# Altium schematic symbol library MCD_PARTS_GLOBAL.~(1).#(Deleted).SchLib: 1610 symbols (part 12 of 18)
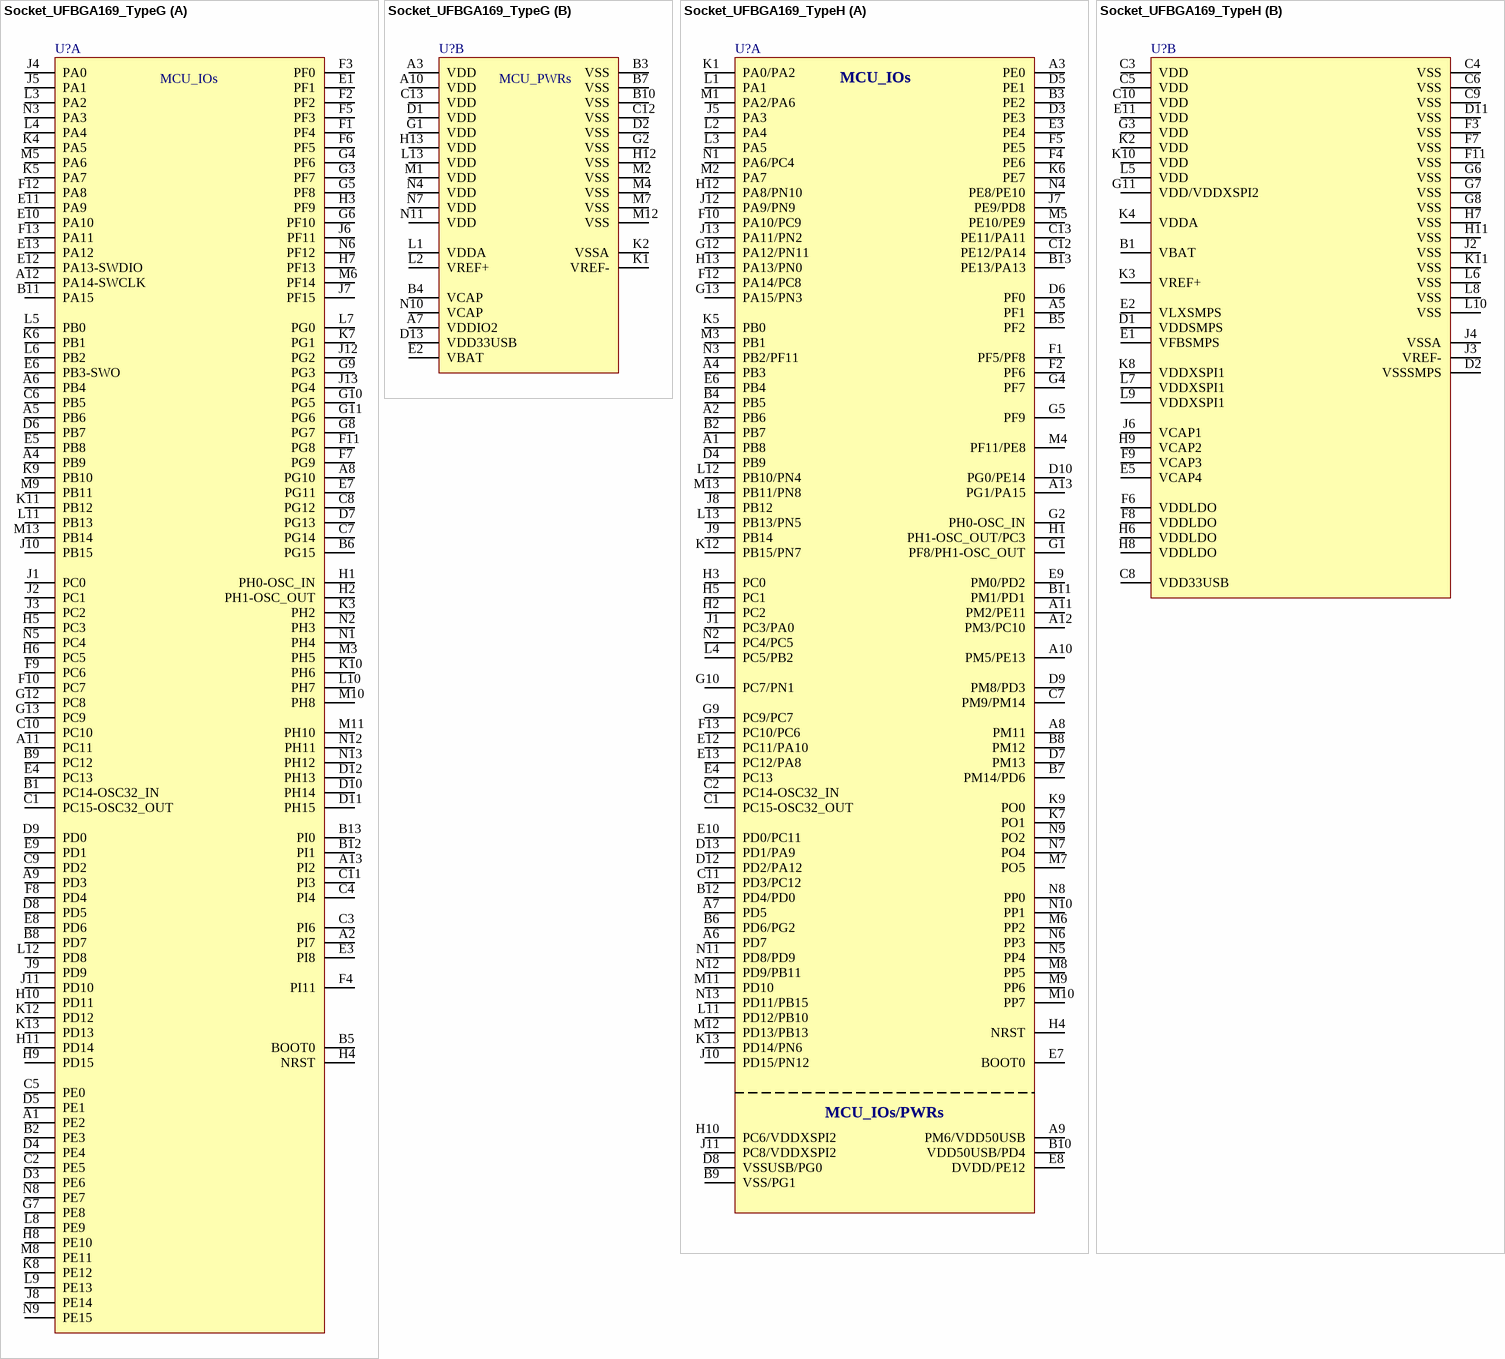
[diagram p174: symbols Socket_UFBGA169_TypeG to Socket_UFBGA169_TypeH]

## Socket_UFBGA169_TypeG
designator U?
part A pins: A1 PE2, A2 PI7, A4 PB9, A5 PB6, A6 PB4, A8 PG10, A9 PD3, A11 PC11, A12 PA14-SWCLK, A13 PI2, B1 PC14-OSC32_IN, B2 PE3, B5 BOOT0, B6 PG15, B8 PD7, B9 PC12, B11 PA15, B12 PI1, B13 PI0, C1 PC15-OSC32_OUT, C2 PE5, C3 PI6, C4 PI4, C5 PE0, C6 PB5, C7 PG14, C8 PG12, C9 PD2, C10 PC10, C11 PI3, D3 PE6, D4 PE4, D5 PE1, D6 PB7, D7 PG13, D8 PD5, D9 PD0, D10 PH14, D11 PH15, D12 PH13, E1 PF1, E3 PI8, E4 PC13, E5 PB8, E6 PB3-SWO, E7 PG11, E8 PD6, E9 PD1, E10 PA10, E11 PA9, E12 PA13-SWDIO, E13 PA12, F1 PF4, F2 PF2, F3 PF0, F4 PI11, F5 PF3, F6 PF5, F7 PG9, F8 PD4, F9 PC6, F10 PC7, F11 PG8, F12 PA8, F13 PA11, G3 PF7, G4 PF6, G5 PF8, G6 PF10, G7 PE8, G8 PG7, G9 PG3, G10 PG5, G11 PG6, G12 PC8, G13 PC9, H1 PH0-OSC_IN, H2 PH1-OSC_OUT, H3 PF9, H4 NRST, H5 PC3, H6 PC5, H7 PF13, H8 PE10, H9 PD15, H10 PD11, H11 PD14, J1 PC0, J2 PC1, J3 PC2, J4 PA0, J5 PA1, J6 PF11, J7 PF15, J8 PE14, J9 PD9, J10 PB15, J11 PD10, J12 PG2, J13 PG4, K3 PH2, K4 PA5, K5 PA7, K6 PB1, K7 PG1, K8 PE12, K9 PB10, K10 PH6, K11 PB12, K12 PD12, K13 PD13, L3 PA2, L4 PA4, L5 PB0, L6 PB2, L7 PG0, L8 PE9, L9 PE13, L10 PH7, L11 PB13, L12 PD8, M3 PH5, M5 PA6, M6 PF14, M8 PE11, M9 PB11, M10 PH8, M11 PH10, M13 PB14, N1 PH4, N2 PH3, N3 PA3, N5 PC4, N6 PF12, N8 PE7, N9 PE15, N12 PH11, N13 PH12
part B pins: A3 VDD, A7 VDDIO2, A10 VDD, B3 VSS, B4 VCAP, B7 VSS, B10 VSS, C12 VSS, C13 VDD, D1 VDD, D2 VSS, D13 VDD33USB, E2 VBAT, G1 VDD, G2 VSS, H12 VSS, H13 VDD, K1 VREF-, K2 VSSA, L1 VDDA, L2 VREF+, L13 VDD, M1 VDD, M2 VSS, M4 VSS, M7 VSS, M12 VSS, N4 VDD, N7 VDD, N10 VCAP, N11 VDD

## Socket_UFBGA169_TypeH
designator U?
part A pins: A1 PB8, A2 PB6, A3 PE0, A4 PB3, A5 PF1, A6 PD7, A7 PD5, A8 PM11, A9 PM6/VDD50USB, A10 PM5/PE13, A11 PM2/PE11, A12 PM3/PC10, A13 PG1/PA15, B2 PB7, B3 PE2, B4 PB5, B5 PF2, B6 PD6/PG2, B7 PM14/PD6, B8 PM12, B9 VSS/PG1, B10 VDD50USB/PD4, B11 PM1/PD1, B12 PD4/PD0, B13 PE13/PA13, C1 PC15-OSC32_OUT, C2 PC14-OSC32_IN, C7 PM9/PM14, C11 PD3/PC12, C12 PE12/PA14, C13 PE11/PA11, D3 PE3, D4 PB9, D5 PE1, D6 PF0, D7 PM13, D8 VSSUSB/PG0, D9 PM8/PD3, D10 PG0/PE14, D12 PD2/PA12, D13 PD1/PA9, E3 PE4, E4 PC13, E6 PB4, E7 BOOT0, E8 DVDD/PE12, E9 PM0/PD2, E10 PD0/PC11, E12 PC11/PA10, E13 PC12/PA8, F1 PF5/PF8, F2 PF6, F4 PE6, F5 PE5, F10 PA10/PC9, F12 PA14/PC8, F13 PC10/PC6, G1 PF8/PH1-OSC_OUT, G2 PH0-OSC_IN, G4 PF7, G5 PF9, G9 PC9/PC7, G10 PC7/PN1, G12 PA12/PN11, G13 PA15/PN3, H1 PH1-OSC_OUT/PC3, H2 PC2, H3 PC0, H4 NRST, H5 PC1, H10 PC6/VDDXSPI2, H12 PA8/PN10, H13 PA13/PN0, J1 PC3/PA0, J5 PA3, J7 PE9/PD8, J8 PB12, J9 PB14, J10 PD15/PN12, J11 PC8/VDDXSPI2, J12 PA9/PN9, J13 PA11/PN2, K1 PA0/PA2, K5 PB0, K6 PE7, K7 PO1, K9 PO0, K12 PB15/PN7, K13 PD14/PN6, L1 PA1, L2 PA4, L3 PA5, L4 PC5/PB2, L11 PD12/PB10, L12 PB10/PN4, L13 PB13/PN5, M1 PA2/PA6, M2 PA7, M3 PB1, M4 PF11/PE8, M5 PE10/PE9, M6 PP2, M7 PO5, M8 PP5, M9 PP6, M10 PP7, M11 PD10, M12 PD13/PB13, M13 PB11/PN8, N1 PA6/PC4, N2 PC4/PC5, N3 PB2/PF11, N4 PE8/PE10, N5 PP4, N6 PP3, N7 PO4, N8 PP0, N9 PO2, N10 PP1, N11 PD8/PD9, N12 PD9/PB11, N13 PD11/PB15
part B pins: B1 VBAT, C3 VDD, C4 VSS, C5 VDD, C6 VSS, C8 VDD33USB, C9 VSS, C10 VDD, D1 VDDSMPS, D2 VSSSMPS, D11 VSS, E1 VFBSMPS, E2 VLXSMPS, E5 VCAP4, E11 VDD, F3 VSS, F6 VDDLDO, F7 VSS, F8 VDDLDO, F9 VCAP3, F11 VSS, G3 VDD, G6 VSS, G7 VSS, G8 VSS, G11 VDD/VDDXSPI2, H6 VDDLDO, H7 VSS, H8 VDDLDO, H9 VCAP2, H11 VSS, J2 VSS, J3 VREF-, J4 VSSA, J6 VCAP1, K2 VDD, K3 VREF+, K4 VDDA, K8 VDDXSPI1, K10 VDD, K11 VSS, L5 VDD, L6 VSS, L7 VDDXSPI1, L8 VSS, L9 VDDXSPI1, L10 VSS

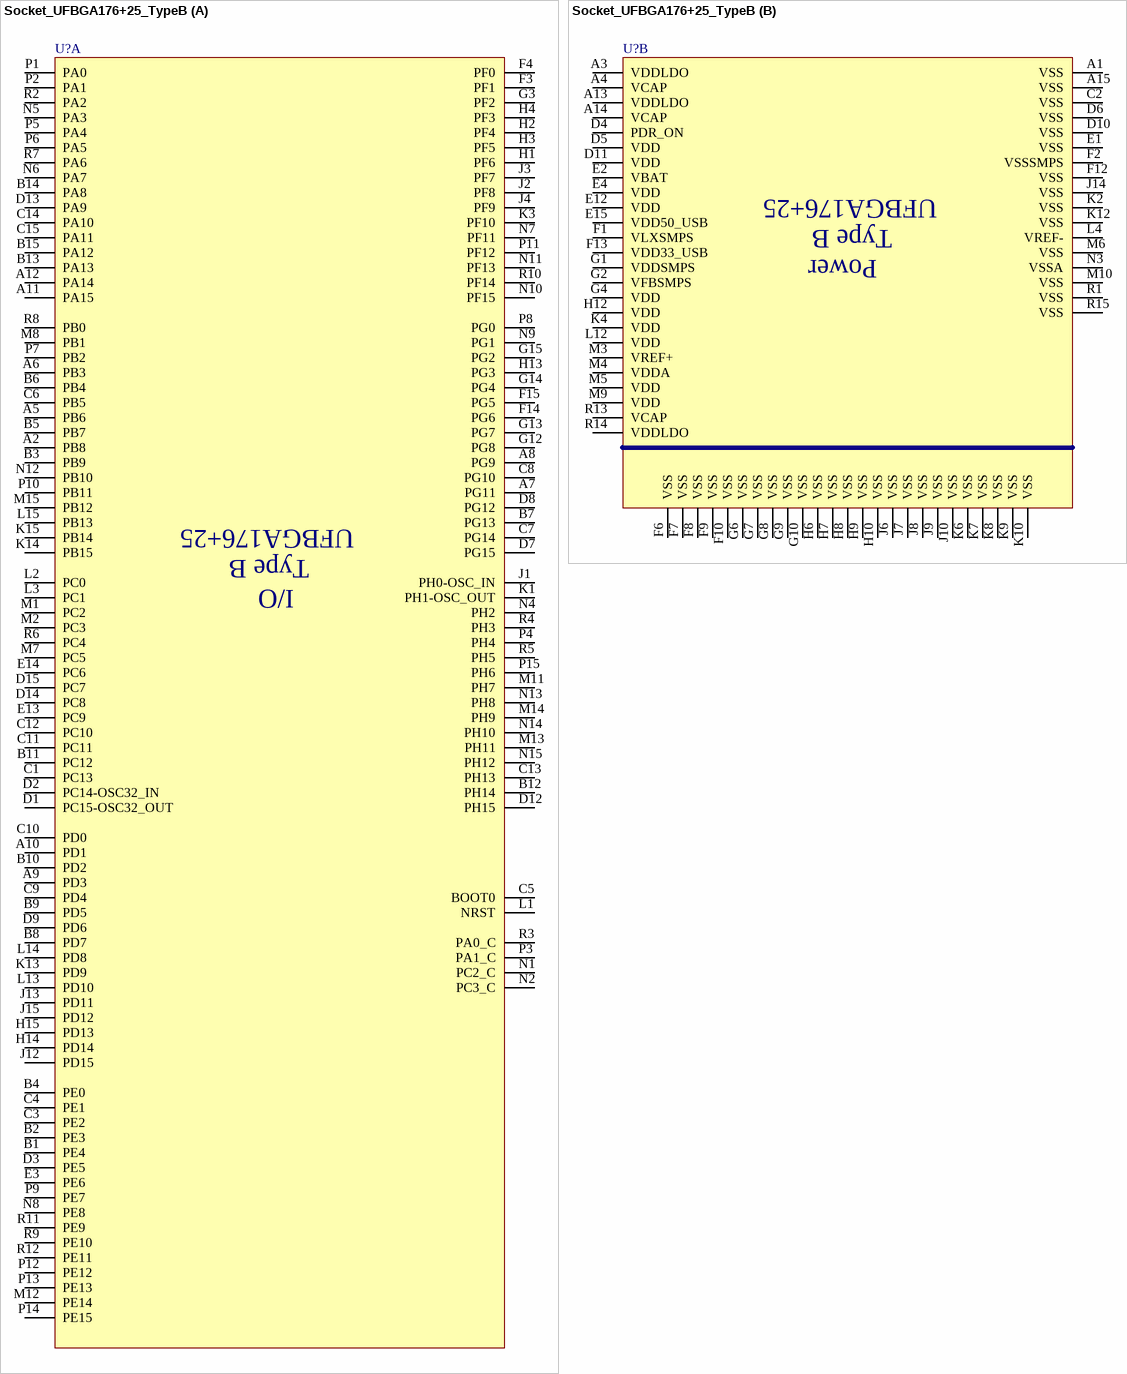
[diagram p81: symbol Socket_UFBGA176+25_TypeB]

## Socket_UFBGA176+25_TypeB
designator U?
part A pins: A2 PB8, A5 PB6, A6 PB3, A7 PG11, A8 PG9, A9 PD3, A10 PD1, A11 PA15, A12 PA14, B1 PE4, B2 PE3, B3 PB9, B4 PE0, B5 PB7, B6 PB4, B7 PG13, B8 PD7, B9 PD5, B10 PD2, B11 PC12, B12 PH14, B13 PA13, B14 PA8, B15 PA12, C1 PC13, C3 PE2, C4 PE1, C5 BOOT0, C6 PB5, C7 PG14, C8 PG10, C9 PD4, C10 PD0, C11 PC11, C12 PC10, C13 PH13, C14 PA10, C15 PA11, D1 PC15-OSC32_OUT, D2 PC14-OSC32_IN, D3 PE5, D7 PG15, D8 PG12, D9 PD6, D12 PH15, D13 PA9, D14 PC8, D15 PC7, E3 PE6, E13 PC9, E14 PC6, F3 PF1, F4 PF0, F14 PG6, F15 PG5, G3 PF2, G12 PG8, G13 PG7, G14 PG4, G15 PG2, H1 PF6, H2 PF4, H3 PF5, H4 PF3, H13 PG3, H14 PD14, H15 PD13, J1 PH0-OSC_IN, J2 PF8, J3 PF7, J4 PF9, J12 PD15, J13 PD11, J15 PD12, K1 PH1-OSC_OUT, K3 PF10, K13 PD9, K14 PB15, K15 PB14, L1 NRST, L2 PC0, L3 PC1, L13 PD10, L14 PD8, L15 PB13, M1 PC2, M2 PC3, M7 PC5, M8 PB1, M11 PH7, M12 PE14, M13 PH11, M14 PH9, M15 PB12, N1 PC2_C, N2 PC3_C, N4 PH2, N5 PA3, N6 PA7, N7 PF11, N8 PE8, N9 PG1, N10 PF15, N11 PF13, N12 PB10, N13 PH8, N14 PH10, N15 PH12, P1 PA0, P2 PA1, P3 PA1_C, P4 PH4, P5 PA4, P6 PA5, P7 PB2, P8 PG0, P9 PE7, P10 PB11, P11 PF12, P12 PE12, P13 PE13, P14 PE15, P15 PH6, R2 PA2, R3 PA0_C, R4 PH3, R5 PH5, R6 PC4, R7 PA6, R8 PB0, R9 PE10, R10 PF14, R11 PE9, R12 PE11
part B pins: A1 VSS, A3 VDDLDO, A4 VCAP, A13 VDDLDO, A14 VCAP, A15 VSS, C2 VSS, D4 PDR_ON, D5 VDD, D6 VSS, D10 VSS, D11 VDD, E1 VSS, E2 VBAT, E4 VDD, E12 VDD, E15 VDD50_USB, F1 VLXSMPS, F2 VSSSMPS, F6 VSS, F7 VSS, F8 VSS, F9 VSS, F10 VSS, F12 VSS, F13 VDD33_USB, G1 VDDSMPS, G2 VFBSMPS, G4 VDD, G6 VSS, G7 VSS, G8 VSS, G9 VSS, G10 VSS, H6 VSS, H7 VSS, H8 VSS, H9 VSS, H10 VSS, H12 VDD, J6 VSS, J7 VSS, J8 VSS, J9 VSS, J10 VSS, J14 VSS, K2 VSS, K4 VDD, K6 VSS, K7 VSS, K8 VSS, K9 VSS, K10 VSS, K12 VSS, L4 VREF-, L12 VDD, M3 VREF+, M4 VDDA, M5 VDD, M6 VSS, M9 VDD, M10 VSS, N3 VSSA, R1 VSS, R13 VCAP, R14 VDDLDO, R15 VSS

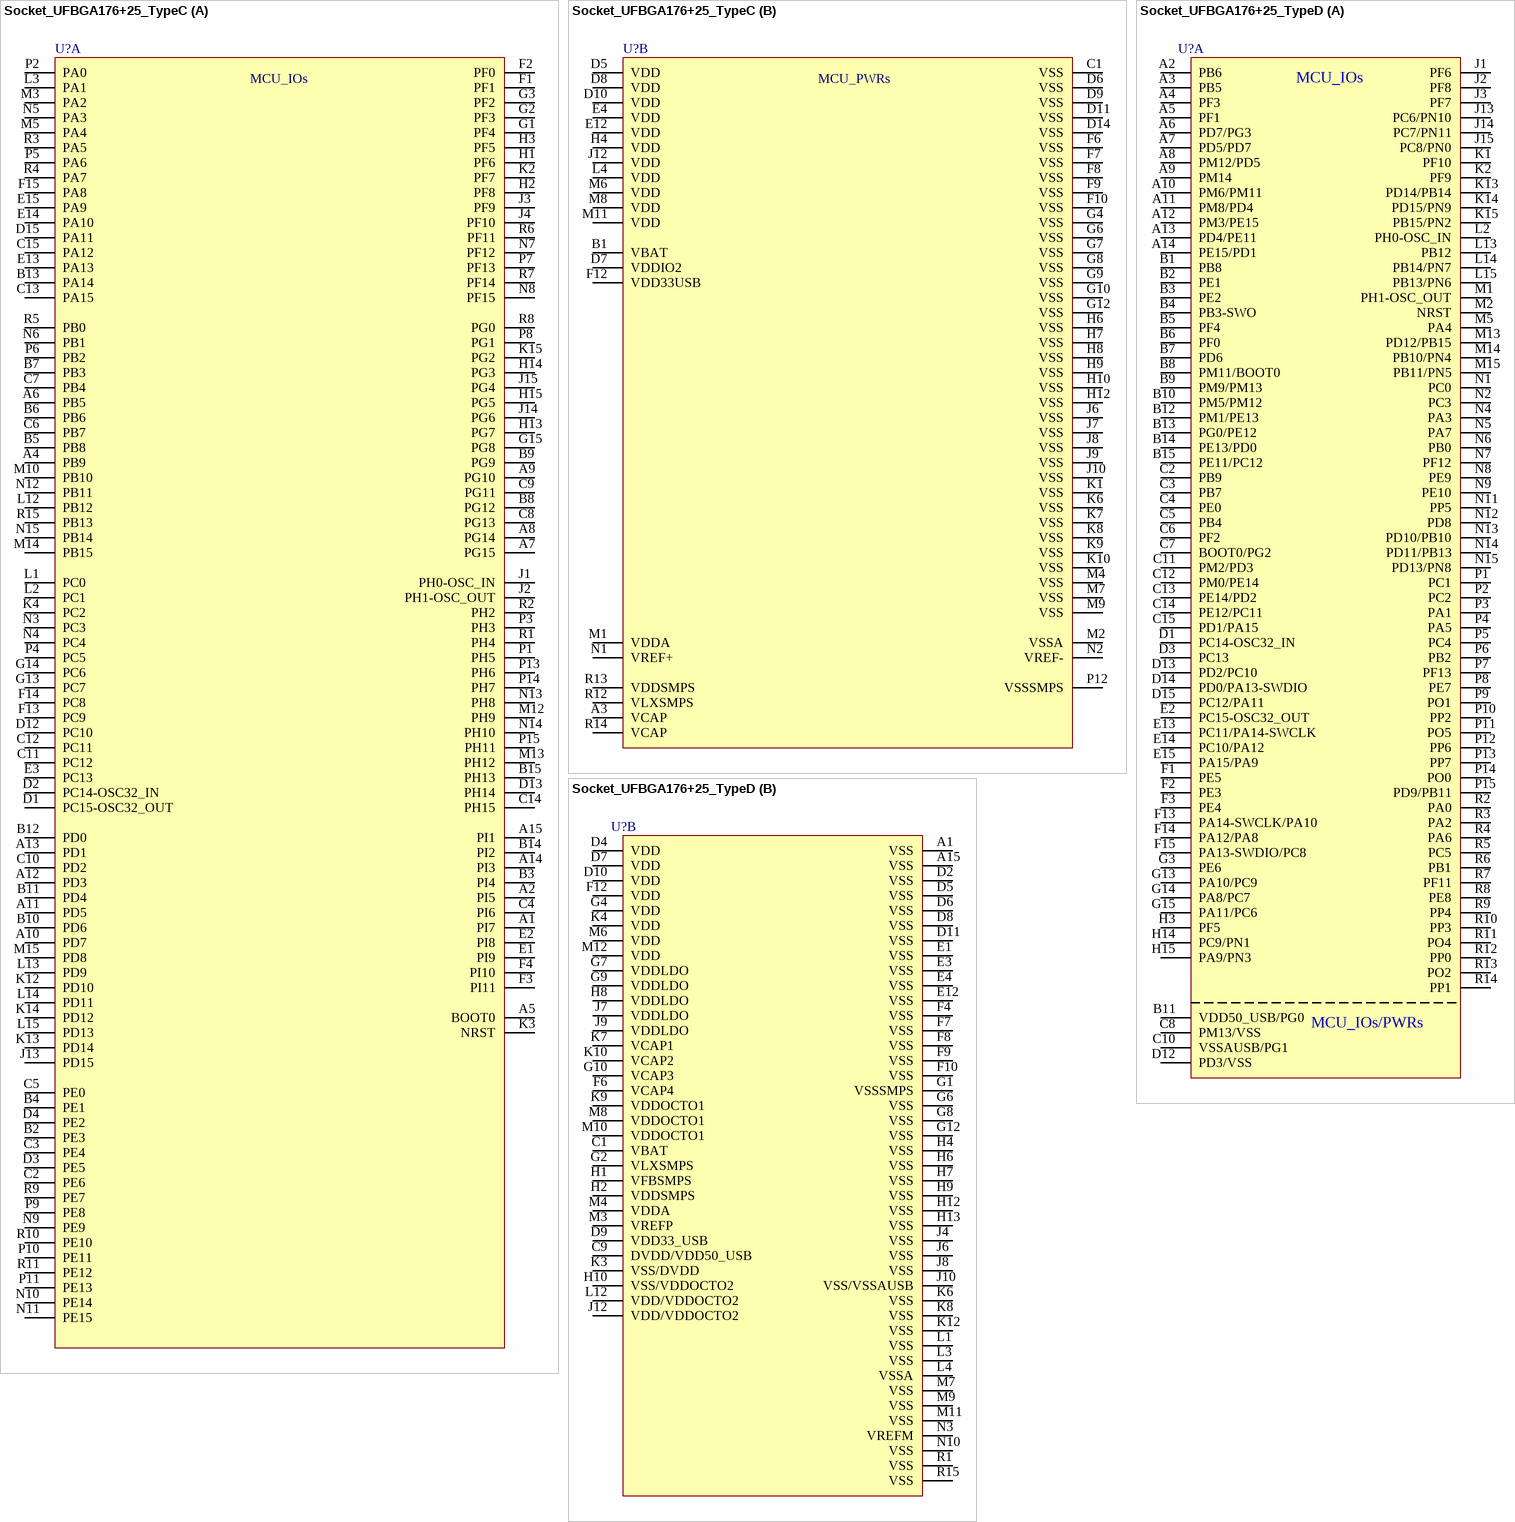
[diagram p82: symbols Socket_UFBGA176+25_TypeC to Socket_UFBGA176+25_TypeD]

## Socket_UFBGA176+25_TypeC
designator U?
part A pins: A1 PI7, A2 PI5, A4 PB9, A5 BOOT0, A6 PB5, A7 PG15, A8 PG14, A9 PG10, A10 PD7, A11 PD5, A12 PD3, A13 PD1, A14 PI3, A15 PI1, B2 PE3, B3 PI4, B4 PE1, B5 PB8, B6 PB6, B7 PB3, B8 PG12, B9 PG9, B10 PD6, B11 PD4, B12 PD0, B13 PA14, B14 PI2, B15 PH13, C2 PE6, C3 PE4, C4 PI6, C5 PE0, C6 PB7, C7 PB4, C8 PG13, C9 PG11, C10 PD2, C11 PC12, C12 PC11, C13 PA15, C14 PH15, C15 PA12, D1 PC15-OSC32_OUT, D2 PC14-OSC32_IN, D3 PE5, D4 PE2, D12 PC10, D13 PH14, D15 PA11, E1 PI9, E2 PI8, E3 PC13, E13 PA13, E14 PA10, E15 PA9, F1 PF1, F2 PF0, F3 PI11, F4 PI10, F13 PC9, F14 PC8, F15 PA8, G1 PF4, G2 PF3, G3 PF2, G13 PC7, G14 PC6, G15 PG8, H1 PF6, H2 PF8, H3 PF5, H13 PG7, H14 PG3, H15 PG5, J1 PH0-OSC_IN, J2 PH1-OSC_OUT, J3 PF9, J4 PF10, J13 PD15, J14 PG6, J15 PG4, K2 PF7, K3 NRST, K4 PC2, K12 PD10, K13 PD14, K14 PD12, K15 PG2, L1 PC0, L2 PC1, L3 PA1, L12 PB12, L13 PD9, L14 PD11, L15 PD13, M3 PA2, M5 PA4, M10 PB10, M12 PH9, M13 PH12, M14 PB15, M15 PD8, N3 PC3, N4 PC4, N5 PA3, N6 PB1, N7 PF12, N8 PF15, N9 PE9, N10 PE14, N11 PE15, N12 PB11, N13 PH8, N14 PH10, N15 PB14, P1 PH5, P2 PA0, P3 PH3, P4 PC5, P5 PA6, P6 PB2, P7 PF13, P8 PG1, P9 PE8, P10 PE11, P11 PE13, P13 PH6, P14 PH7, P15 PH11, R1 PH4, R2 PH2, R3 PA5, R4 PA7, R5 PB0, R6 PF11, R7 PF14, R8 PG0, R9 PE7, R10 PE10, R11 PE12, R15 PB13
part B pins: A3 VCAP, B1 VBAT, C1 VSS, D5 VDD, D6 VSS, D7 VDDIO2, D8 VDD, D9 VSS, D10 VDD, D11 VSS, D14 VSS, E4 VDD, E12 VDD, F6 VSS, F7 VSS, F8 VSS, F9 VSS, F10 VSS, F12 VDD33USB, G4 VSS, G6 VSS, G7 VSS, G8 VSS, G9 VSS, G10 VSS, G12 VSS, H4 VDD, H6 VSS, H7 VSS, H8 VSS, H9 VSS, H10 VSS, H12 VSS, J6 VSS, J7 VSS, J8 VSS, J9 VSS, J10 VSS, J12 VDD, K1 VSS, K6 VSS, K7 VSS, K8 VSS, K9 VSS, K10 VSS, L4 VDD, M1 VDDA, M2 VSSA, M4 VSS, M6 VDD, M7 VSS, M8 VDD, M9 VSS, M11 VDD, N1 VREF+, N2 VREF-, P12 VSSSMPS, R12 VLXSMPS, R13 VDDSMPS, R14 VCAP

## Socket_UFBGA176+25_TypeD
designator U?
part A pins: A2 PB6, A3 PB5, A4 PF3, A5 PF1, A6 PD7/PG3, A7 PD5/PD7, A8 PM12/PD5, A9 PM14, A10 PM6/PM11, A11 PM8/PD4, A12 PM3/PE15, A13 PD4/PE11, A14 PE15/PD1, B1 PB8, B2 PE1, B3 PE2, B4 PB3-SWO, B5 PF4, B6 PF0, B7 PD6, B8 PM11/BOOT0, B9 PM9/PM13, B10 PM5/PM12, B11 VDD50_USB/PG0, B12 PM1/PE13, B13 PG0/PE12, B14 PE13/PD0, B15 PE11/PC12, C2 PB9, C3 PB7, C4 PE0, C5 PB4, C6 PF2, C7 BOOT0/PG2, C8 PM13/VSS, C10 VSSAUSB/PG1, C11 PM2/PD3, C12 PM0/PE14, C13 PE14/PD2, C14 PE12/PC11, C15 PD1/PA15, D1 PC14-OSC32_IN, D3 PC13, D12 PD3/VSS, D13 PD2/PC10, D14 PD0/PA13-SWDIO, D15 PC12/PA11, E2 PC15-OSC32_OUT, E13 PC11/PA14-SWCLK, E14 PC10/PA12, E15 PA15/PA9, F1 PE5, F2 PE3, F3 PE4, F13 PA14-SWCLK/PA10, F14 PA12/PA8, F15 PA13-SWDIO/PC8, G3 PE6, G13 PA10/PC9, G14 PA8/PC7, G15 PA11/PC6, H3 PF5, H14 PC9/PN1, H15 PA9/PN3, J1 PF6, J2 PF8, J3 PF7, J13 PC6/PN10, J14 PC7/PN11, J15 PC8/PN0, K1 PF10, K2 PF9, K13 PD14/PB14, K14 PD15/PN9, K15 PB15/PN2, L2 PH0-OSC_IN, L13 PB12, L14 PB14/PN7, L15 PB13/PN6, M1 PH1-OSC_OUT, M2 NRST, M5 PA4, M13 PD12/PB15, M14 PB10/PN4, M15 PB11/PN5, N1 PC0, N2 PC3, N4 PA3, N5 PA7, N6 PB0, N7 PF12, N8 PE9, N9 PE10, N11 PP5, N12 PD8, N13 PD10/PB10, N14 PD11/PB13, N15 PD13/PN8, P1 PC1, P2 PC2, P3 PA1, P4 PA5, P5 PC4, P6 PB2, P7 PF13, P8 PE7, P9 PO1, P10 PP2, P11 PO5, P12 PP6, P13 PP7, P14 PO0, P15 PD9/PB11, R2 PA0, R3 PA2, R4 PA6, R5 PC5, R6 PB1, R7 PF11, R8 PE8, R9 PP4, R10 PP3, R11 PO4, R12 PP0, R13 PO2, R14 PP1
part B pins: A1 VSS, A15 VSS, C1 VBAT, C9 DVDD/VDD50_USB, D2 VSS, D4 VDD, D5 VSS, D6 VSS, D7 VDD, D8 VSS, D9 VDD33_USB, D10 VDD, D11 VSS, E1 VSS, E3 VSS, E4 VSS, E12 VSS, F4 VSS, F6 VCAP4, F7 VSS, F8 VSS, F9 VSS, F10 VSS, F12 VDD, G1 VSSSMPS, G2 VLXSMPS, G4 VDD, G6 VSS, G7 VDDLDO, G8 VSS, G9 VDDLDO, G10 VCAP3, G12 VSS, H1 VFBSMPS, H2 VDDSMPS, H4 VSS, H6 VSS, H7 VSS, H8 VDDLDO, H9 VSS, H10 VSS/VDDOCTO2, H12 VSS, H13 VSS, J4 VSS, J6 VSS, J7 VDDLDO, J8 VSS, J9 VDDLDO, J10 VSS/VSSAUSB, J12 VDD/VDDOCTO2, K3 VSS/DVDD, K4 VDD, K6 VSS, K7 VCAP1, K8 VSS, K9 VDDOCTO1, K10 VCAP2, K12 VSS, L1 VSS, L3 VSS, L4 VSSA, L12 VDD/VDDOCTO2, M3 VREFP, M4 VDDA, M6 VDD, M7 VSS, M8 VDDOCTO1, M9 VSS, M10 VDDOCTO1, M11 VSS, M12 VDD, N3 VREFM, N10 VSS, R1 VSS, R15 VSS

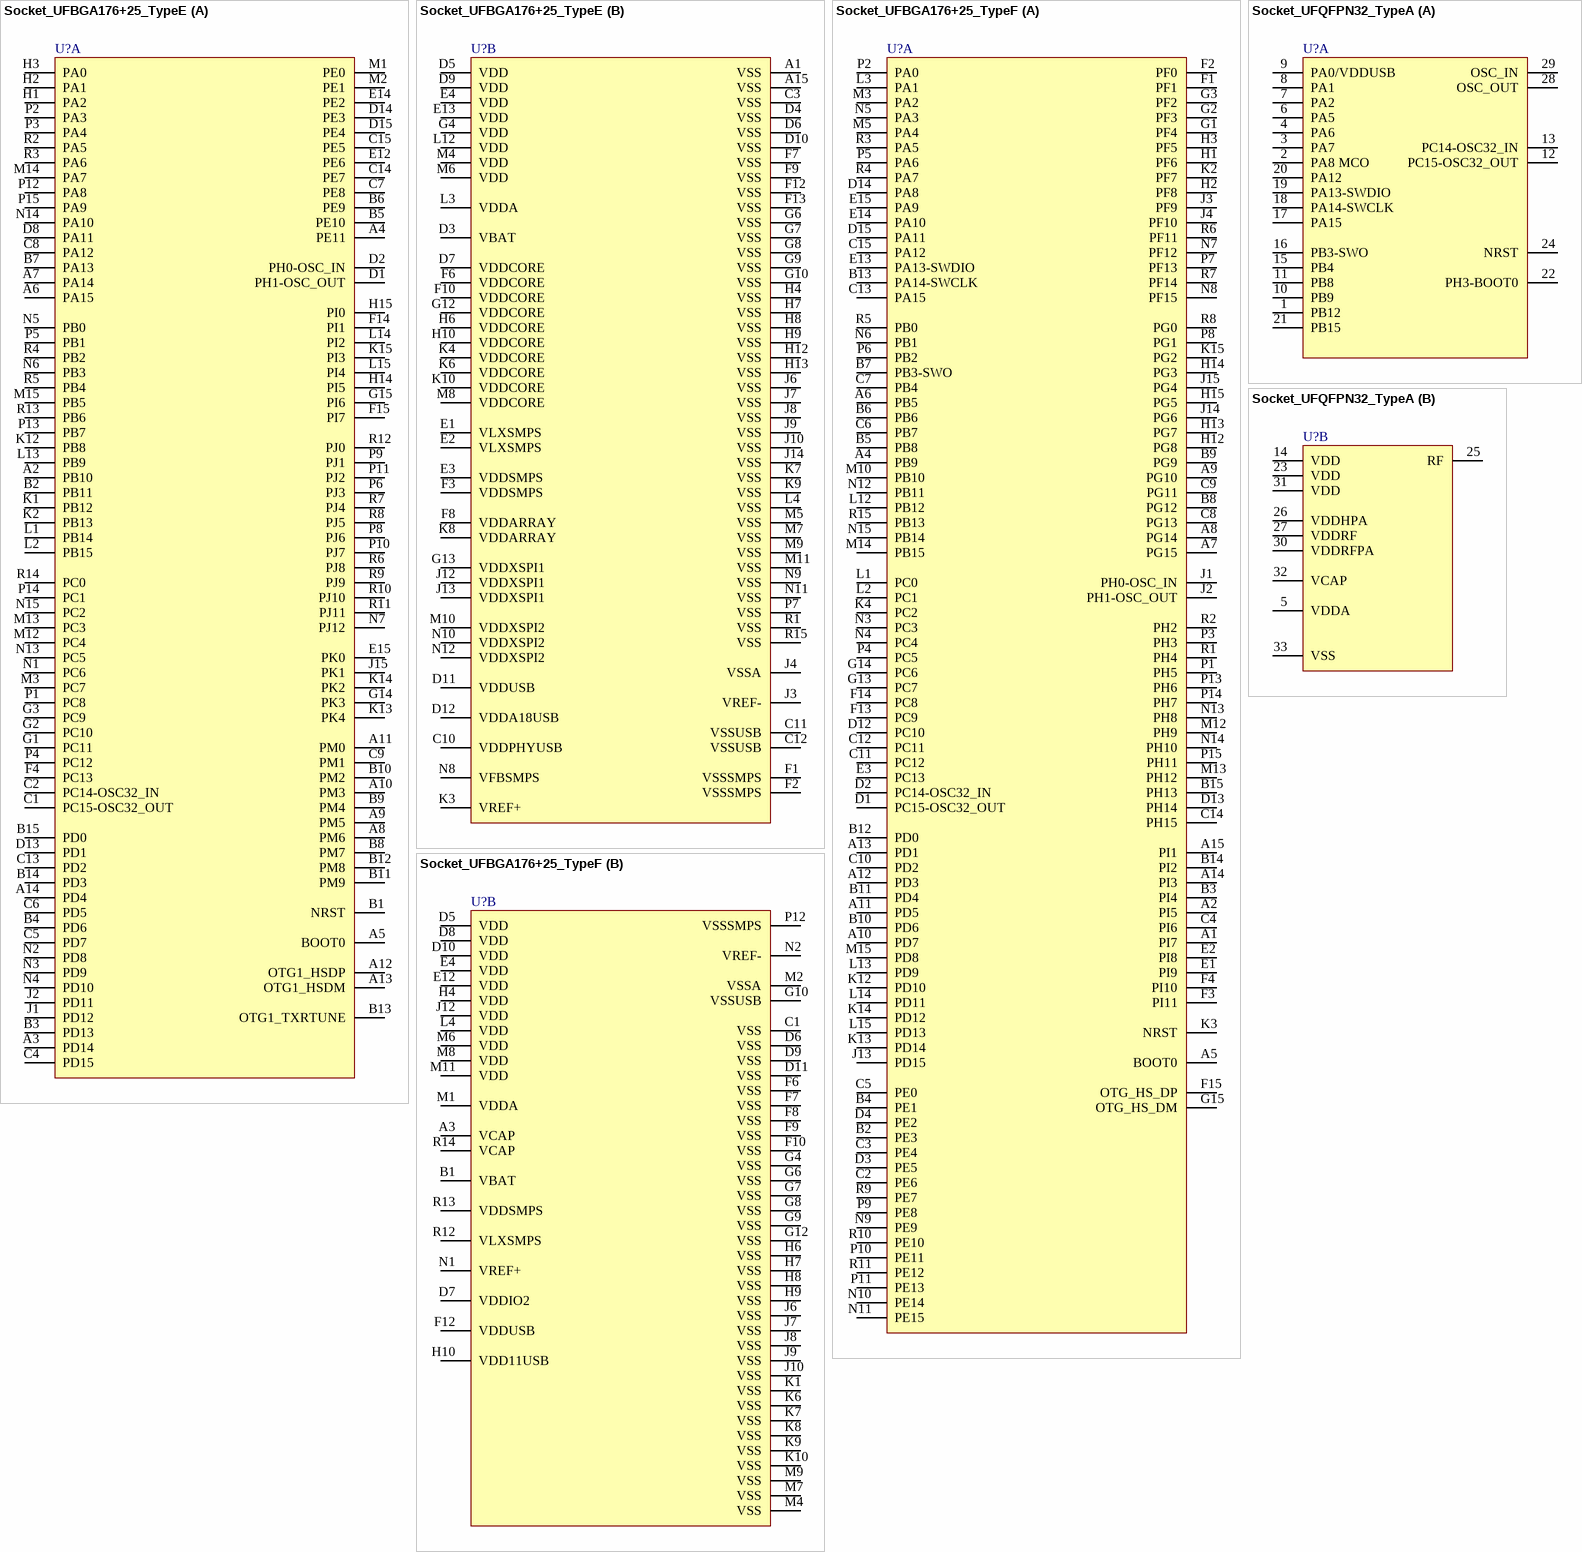
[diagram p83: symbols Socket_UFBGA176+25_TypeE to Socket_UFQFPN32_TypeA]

## Socket_UFBGA176+25_TypeE
designator U?
part A pins: A2 PB10, A3 PD14, A4 PE11, A5 BOOT0, A6 PA15, A7 PA14, A8 PM6, A9 PM5, A10 PM3, A11 PM0, A12 OTG1_HSDP, A13 OTG1_HSDM, A14 PD4, B1 NRST, B2 PB11, B3 PD13, B4 PD6, B5 PE10, B6 PE9, B7 PA13, B8 PM7, B9 PM4, B10 PM2, B11 PM9, B12 PM8, B13 OTG1_TXRTUNE, B14 PD3, B15 PD0, C1 PC15-OSC32_OUT, C2 PC14-OSC32_IN, C4 PD15, C5 PD7, C6 PD5, C7 PE8, C8 PA12, C9 PM1, C13 PD2, C14 PE7, C15 PE5, D1 PH1-OSC_OUT, D2 PH0-OSC_IN, D8 PA11, D13 PD1, D14 PE3, D15 PE4, E12 PE6, E14 PE2, E15 PK0, F4 PC13, F14 PI1, F15 PI7, G1 PC11, G2 PC10, G3 PC9, G14 PK3, G15 PI6, H1 PA2, H2 PA1, H3 PA0, H14 PI5, H15 PI0, J1 PD12, J2 PD11, J15 PK1, K1 PB12, K2 PB13, K12 PB8, K13 PK4, K14 PK2, K15 PI3, L1 PB14, L2 PB15, L13 PB9, L14 PI2, L15 PI4, M1 PE0, M2 PE1, M3 PC7, M12 PC4, M13 PC3, M14 PA7, M15 PB5, N1 PC6, N2 PD8, N3 PD9, N4 PD10, N5 PB0, N6 PB3, N7 PJ12, N13 PC5, N14 PA10, N15 PC2, P1 PC8, P2 PA3, P3 PA4, P4 PC12, P5 PB1, P6 PJ3, P8 PJ6, P9 PJ1, P10 PJ7, P11 PJ2, P12 PA8, P13 PB7, P14 PC1, P15 PA9, R2 PA5, R3 PA6, R4 PB2, R5 PB4, R6 PJ8, R7 PJ4, R8 PJ5, R9 PJ9, R10 PJ10, R11 PJ11, R12 PJ0, R13 PB6, R14 PC0
part B pins: A1 VSS, A15 VSS, C3 VSS, C10 VDDPHYUSB, C11 VSSUSB, C12 VSSUSB, D3 VBAT, D4 VSS, D5 VDD, D6 VSS, D7 VDDCORE, D9 VDD, D10 VSS, D11 VDDUSB, D12 VDDA18USB, E1 VLXSMPS, E2 VLXSMPS, E3 VDDSMPS, E4 VDD, E13 VDD, F1 VSSSMPS, F2 VSSSMPS, F3 VDDSMPS, F6 VDDCORE, F7 VSS, F8 VDDARRAY, F9 VSS, F10 VDDCORE, F12 VSS, F13 VSS, G4 VDD, G6 VSS, G7 VSS, G8 VSS, G9 VSS, G10 VSS, G12 VDDCORE, G13 VDDXSPI1, H4 VSS, H6 VDDCORE, H7 VSS, H8 VSS, H9 VSS, H10 VDDCORE, H12 VSS, H13 VSS, J3 VREF-, J4 VSSA, J6 VSS, J7 VSS, J8 VSS, J9 VSS, J10 VSS, J12 VDDXSPI1, J13 VDDXSPI1, J14 VSS, K3 VREF+, K4 VDDCORE, K6 VDDCORE, K7 VSS, K8 VDDARRAY, K9 VSS, K10 VDDCORE, L3 VDDA, L4 VSS, L12 VDD, M4 VDD, M5 VSS, M6 VDD, M7 VSS, M8 VDDCORE, M9 VSS, M10 VDDXSPI2, M11 VSS, N8 VFBSMPS, N9 VSS, N10 VDDXSPI2, N11 VSS, N12 VDDXSPI2, P7 VSS, R1 VSS, R15 VSS

## Socket_UFBGA176+25_TypeF
designator U?
part A pins: A1 PI7, A2 PI5, A4 PB9, A5 BOOT0, A6 PB5, A7 PG15, A8 PG14, A9 PG10, A10 PD7, A11 PD5, A12 PD3, A13 PD1, A14 PI3, A15 PI1, B2 PE3, B3 PI4, B4 PE1, B5 PB8, B6 PB6, B7 PB3-SWO, B8 PG12, B9 PG9, B10 PD6, B11 PD4, B12 PD0, B13 PA14-SWCLK, B14 PI2, B15 PH13, C2 PE6, C3 PE4, C4 PI6, C5 PE0, C6 PB7, C7 PB4, C8 PG13, C9 PG11, C10 PD2, C11 PC12, C12 PC11, C13 PA15, C14 PH15, C15 PA12, D1 PC15-OSC32_OUT, D2 PC14-OSC32_IN, D3 PE5, D4 PE2, D12 PC10, D13 PH14, D14 PA8, D15 PA11, E1 PI9, E2 PI8, E3 PC13, E13 PA13-SWDIO, E14 PA10, E15 PA9, F1 PF1, F2 PF0, F3 PI11, F4 PI10, F13 PC9, F14 PC8, F15 OTG_HS_DP, G1 PF4, G2 PF3, G3 PF2, G13 PC7, G14 PC6, G15 OTG_HS_DM, H1 PF6, H2 PF8, H3 PF5, H12 PG8, H13 PG7, H14 PG3, H15 PG5, J1 PH0-OSC_IN, J2 PH1-OSC_OUT, J3 PF9, J4 PF10, J13 PD15, J14 PG6, J15 PG4, K2 PF7, K3 NRST, K4 PC2, K12 PD10, K13 PD14, K14 PD12, K15 PG2, L1 PC0, L2 PC1, L3 PA1, L12 PB12, L13 PD9, L14 PD11, L15 PD13, M3 PA2, M5 PA4, M10 PB10, M12 PH9, M13 PH12, M14 PB15, M15 PD8, N3 PC3, N4 PC4, N5 PA3, N6 PB1, N7 PF12, N8 PF15, N9 PE9, N10 PE14, N11 PE15, N12 PB11, N13 PH8, N14 PH10, N15 PB14, P1 PH5, P2 PA0, P3 PH3, P4 PC5, P5 PA6, P6 PB2, P7 PF13, P8 PG1, P9 PE8, P10 PE11, P11 PE13, P13 PH6, P14 PH7, P15 PH11, R1 PH4, R2 PH2, R3 PA5, R4 PA7, R5 PB0, R6 PF11, R7 PF14, R8 PG0, R9 PE7, R10 PE10, R11 PE12, R15 PB13
part B pins: A3 VCAP, B1 VBAT, C1 VSS, D5 VDD, D6 VSS, D7 VDDIO2, D8 VDD, D9 VSS, D10 VDD, D11 VSS, E4 VDD, E12 VDD, F6 VSS, F7 VSS, F8 VSS, F9 VSS, F10 VSS, F12 VDDUSB, G4 VSS, G6 VSS, G7 VSS, G8 VSS, G9 VSS, G10 VSSUSB, G12 VSS, H4 VDD, H6 VSS, H7 VSS, H8 VSS, H9 VSS, H10 VDD11USB, J6 VSS, J7 VSS, J8 VSS, J9 VSS, J10 VSS, J12 VDD, K1 VSS, K6 VSS, K7 VSS, K8 VSS, K9 VSS, K10 VSS, L4 VDD, M1 VDDA, M2 VSSA, M4 VSS, M6 VDD, M7 VSS, M8 VDD, M9 VSS, M11 VDD, N1 VREF+, N2 VREF-, P12 VSSSMPS, R12 VLXSMPS, R13 VDDSMPS, R14 VCAP

## Socket_UFQFPN32_TypeA
designator U?
part A pins: 1 PB12, 2 PA8 MCO, 3 PA7, 4 PA6, 6 PA5, 7 PA2, 8 PA1, 9 PA0/VDDUSB, 10 PB9, 11 PB8, 12 PC15-OSC32_OUT, 13 PC14-OSC32_IN, 15 PB4, 16 PB3-SWO, 17 PA15, 18 PA14-SWCLK, 19 PA13-SWDIO, 20 PA12, 21 PB15, 22 PH3-BOOT0, 24 NRST, 28 OSC_OUT, 29 OSC_IN
part B pins: 5 VDDA, 14 VDD, 23 VDD, 25 RF, 26 VDDHPA, 27 VDDRF, 30 VDDRFPA, 31 VDD, 32 VCAP, 33 VSS

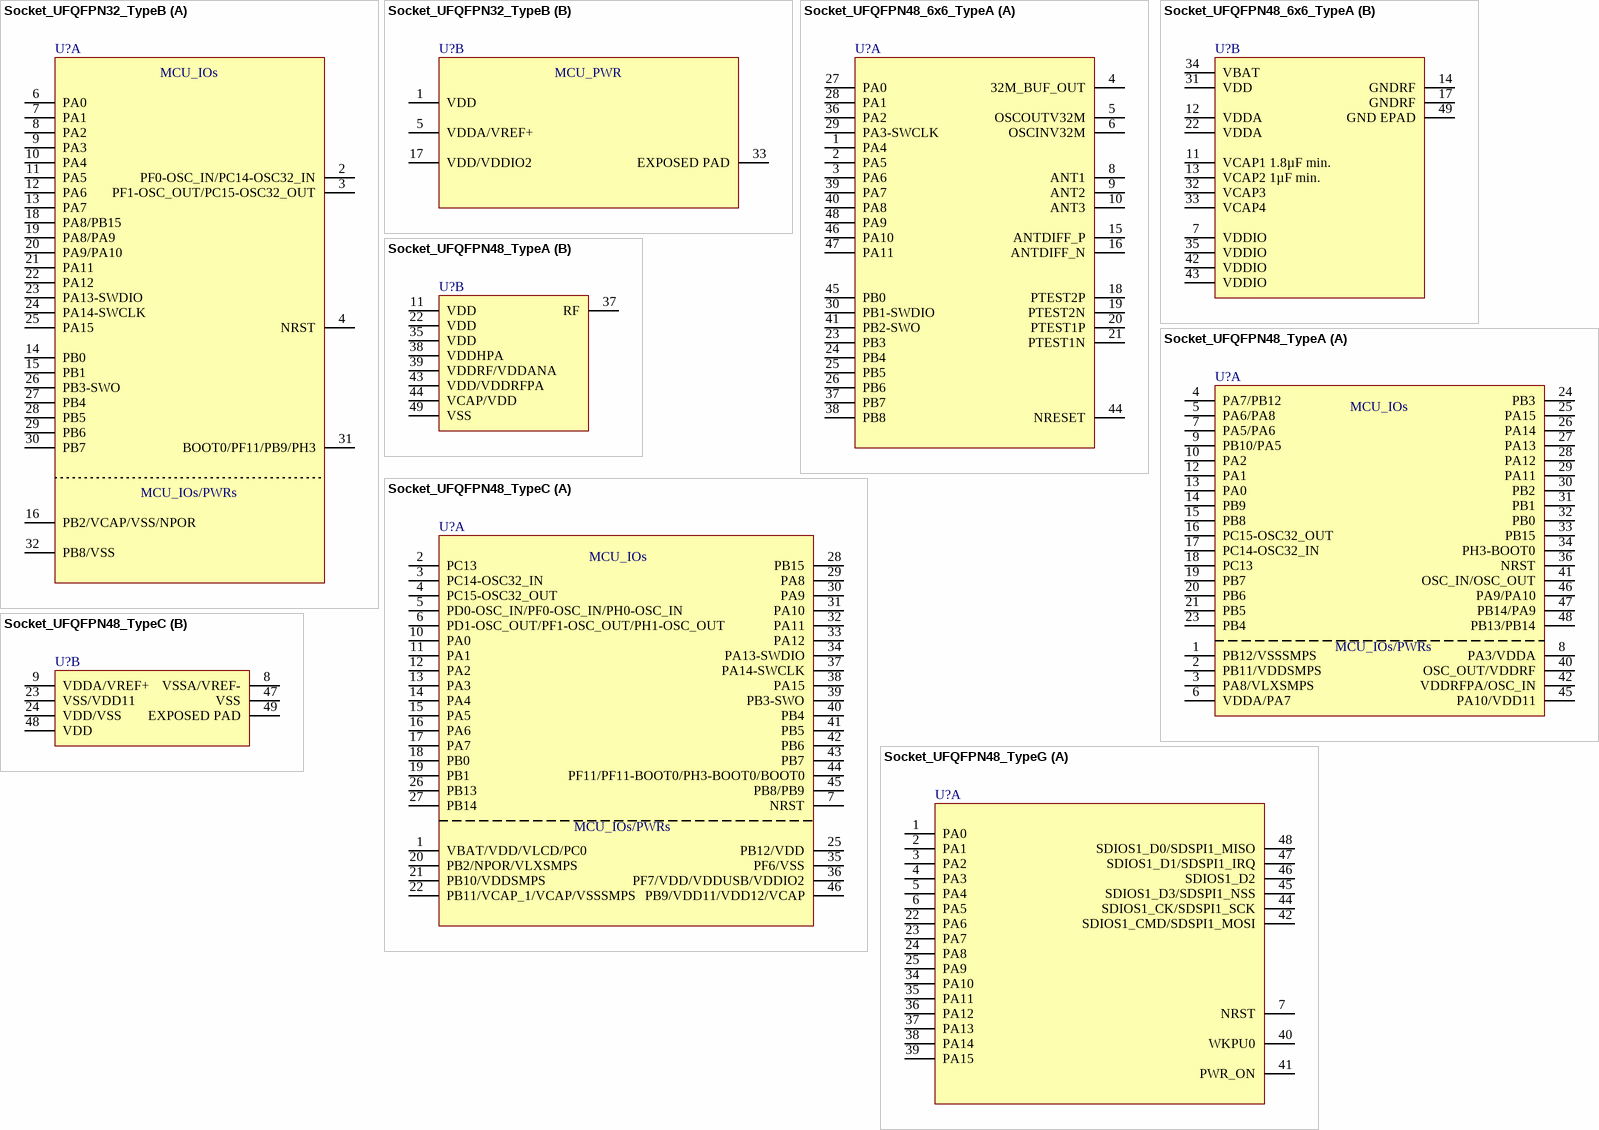
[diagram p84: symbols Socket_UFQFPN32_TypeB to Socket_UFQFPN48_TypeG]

## Socket_UFQFPN32_TypeB
designator U?
part A pins: 2 PF0-OSC_IN/PC14-OSC32_IN, 3 PF1-OSC_OUT/PC15-OSC32_OUT, 4 NRST, 6 PA0, 7 PA1, 8 PA2, 9 PA3, 10 PA4, 11 PA5, 12 PA6, 13 PA7, 14 PB0, 15 PB1, 16 PB2/VCAP/VSS/NPOR, 18 PA8/PB15, 19 PA8/PA9, 20 PA9/PA10, 21 PA11, 22 PA12, 23 PA13-SWDIO, 24 PA14-SWCLK, 25 PA15, 26 PB3-SWO, 27 PB4, 28 PB5, 29 PB6, 30 PB7, 31 BOOT0/PF11/PB9/PH3, 32 PB8/VSS
part B pins: 1 VDD, 5 VDDA/VREF+, 17 VDD/VDDIO2, 33 EXPOSED PAD

## Socket_UFQFPN48_6x6_TypeA
designator U?
part A pins: 1 PA4, 2 PA5, 3 PA6, 4 32M_BUF_OUT, 5 OSCOUTV32M, 6 OSCINV32M, 8 ANT1, 9 ANT2, 10 ANT3, 15 ANTDIFF_P, 16 ANTDIFF_N, 18 PTEST2P, 19 PTEST2N, 20 PTEST1P, 21 PTEST1N, 23 PB3, 24 PB4, 25 PB5, 26 PB6, 27 PA0, 28 PA1, 29 PA3-SWCLK, 30 PB1-SWDIO, 36 PA2, 37 PB7, 38 PB8, 39 PA7, 40 PA8, 41 PB2-SWO, 44 NRESET, 45 PB0, 46 PA10, 47 PA11, 48 PA9
part B pins: 7 VDDIO, 11 VCAP1 1.8µF min., 12 VDDA, 13 VCAP2 1µF min., 14 GNDRF, 17 GNDRF, 22 VDDA, 31 VDD, 32 VCAP3, 33 VCAP4, 34 VBAT, 35 VDDIO, 42 VDDIO, 43 VDDIO, 49 GND EPAD

## Socket_UFQFPN48_TypeA
designator U?
part A pins: 1 PB12/VSSSMPS, 2 PB11/VDDSMPS, 3 PA8/VLXSMPS, 4 PA7/PB12, 5 PA6/PA8, 6 VDDA/PA7, 7 PA5/PA6, 8 PA3/VDDA, 9 PB10/PA5, 10 PA2, 12 PA1, 13 PA0, 14 PB9, 15 PB8, 16 PC15-OSC32_OUT, 17 PC14-OSC32_IN, 18 PC13, 19 PB7, 20 PB6, 21 PB5, 23 PB4, 24 PB3, 25 PA15, 26 PA14, 27 PA13, 28 PA12, 29 PA11, 30 PB2, 31 PB1, 32 PB0, 33 PB15, 34 PH3-BOOT0, 36 NRST, 40 OSC_OUT/VDDRF, 41 OSC_IN/OSC_OUT, 42 VDDRFPA/OSC_IN, 45 PA10/VDD11, 46 PA9/PA10, 47 PB14/PA9, 48 PB13/PB14
part B pins: 11 VDD, 22 VDD, 35 VDD, 37 RF, 38 VDDHPA, 39 VDDRF/VDDANA, 43 VDD/VDDRFPA, 44 VCAP/VDD, 49 VSS

## Socket_UFQFPN48_TypeC
designator U?
part A pins: 1 VBAT/VDD/VLCD/PC0, 2 PC13, 3 PC14-OSC32_IN, 4 PC15-OSC32_OUT, 5 PD0-OSC_IN/PF0-OSC_IN/PH0-OSC_IN, 6 PD1-OSC_OUT/PF1-OSC_OUT/PH1-OSC_OUT, 7 NRST, 10 PA0, 11 PA1, 12 PA2, 13 PA3, 14 PA4, 15 PA5, 16 PA6, 17 PA7, 18 PB0, 19 PB1, 20 PB2/NPOR/VLXSMPS, 21 PB10/VDDSMPS, 22 PB11/VCAP_1/VCAP/VSSSMPS, 25 PB12/VDD, 26 PB13, 27 PB14, 28 PB15, 29 PA8, 30 PA9, 31 PA10, 32 PA11, 33 PA12, 34 PA13-SWDIO, 35 PF6/VSS, 36 PF7/VDD/VDDUSB/VDDIO2, 37 PA14-SWCLK, 38 PA15, 39 PB3-SWO, 40 PB4, 41 PB5, 42 PB6, 43 PB7, 44 PF11/PF11-BOOT0/PH3-BOOT0/BOOT0, 45 PB8/PB9, 46 PB9/VDD11/VDD12/VCAP
part B pins: 8 VSSA/VREF-, 9 VDDA/VREF+, 23 VSS/VDD11, 24 VDD/VSS, 47 VSS, 48 VDD, 49 EXPOSED PAD

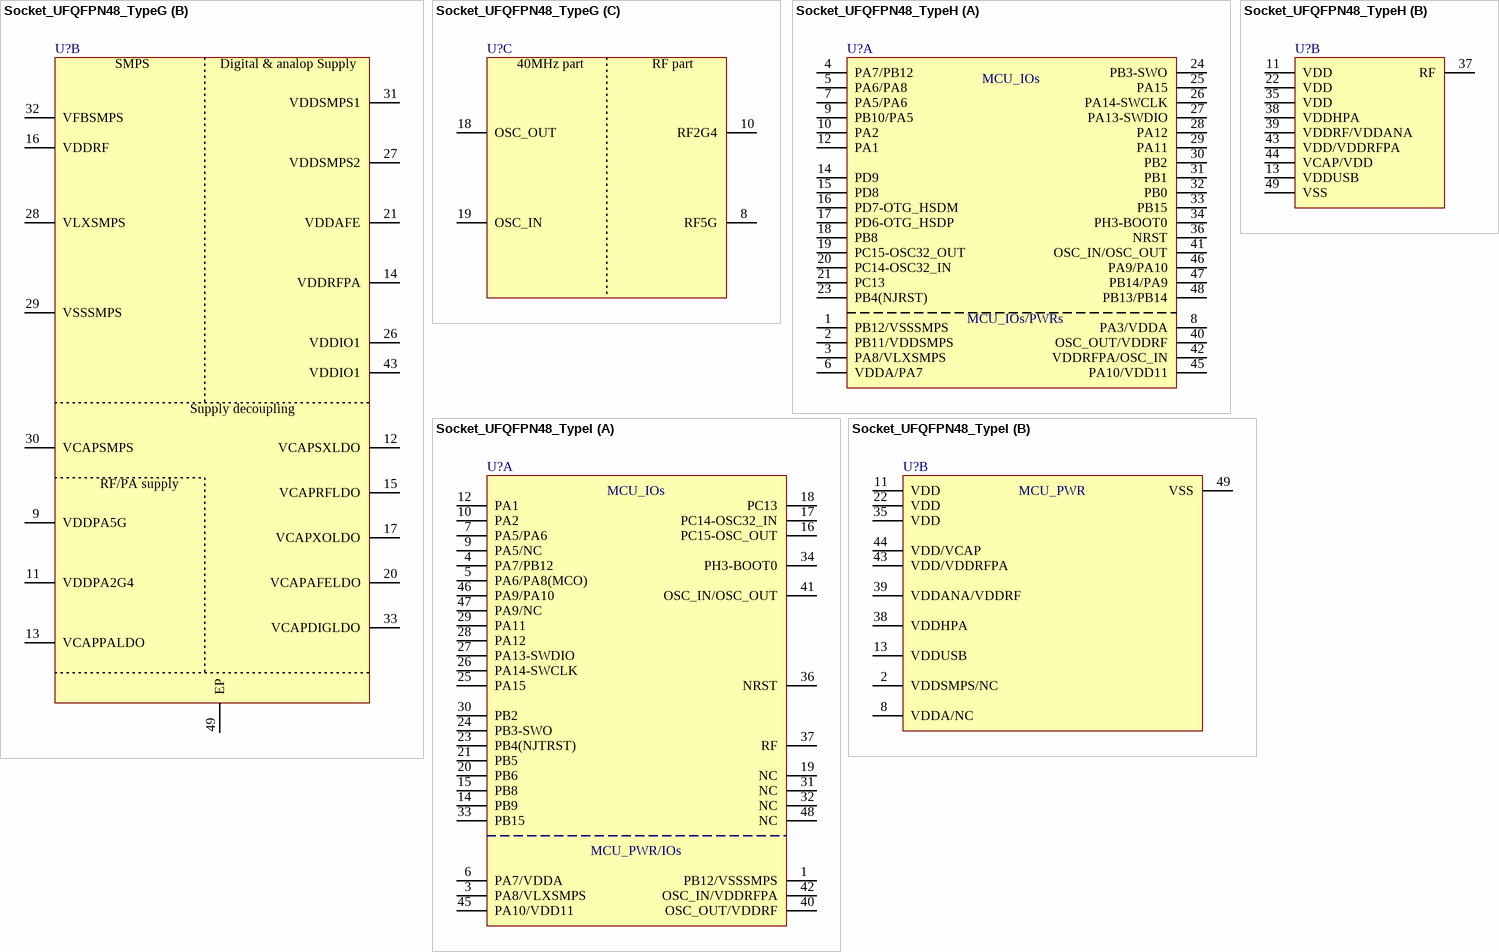
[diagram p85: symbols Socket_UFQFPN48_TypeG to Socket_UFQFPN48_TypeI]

## Socket_UFQFPN48_TypeG
designator U?
part A pins: 1 PA0, 2 PA1, 3 PA2, 4 PA3, 5 PA4, 6 PA5, 7 NRST, 22 PA6, 23 PA7, 24 PA8, 25 PA9, 34 PA10, 35 PA11, 36 PA12, 37 PA13, 38 PA14, 39 PA15, 40 WKPU0, 41 PWR_ON, 42 SDIOS1_CMD/SDSPI1_MOSI, 44 SDIOS1_CK/SDSPI1_SCK, 45 SDIOS1_D3/SDSPI1_NSS, 46 SDIOS1_D2, 47 SDIOS1_D1/SDSPI1_IRQ, 48 SDIOS1_D0/SDSPI1_MISO
part B pins: 9 VDDPA5G, 11 VDDPA2G4, 12 VCAPSXLDO, 13 VCAPPALDO, 14 VDDRFPA, 15 VCAPRFLDO, 16 VDDRF, 17 VCAPXOLDO, 20 VCAPAFELDO, 21 VDDAFE, 26 VDDIO1, 27 VDDSMPS2, 28 VLXSMPS, 29 VSSSMPS, 30 VCAPSMPS, 31 VDDSMPS1, 32 VFBSMPS, 33 VCAPDIGLDO, 43 VDDIO1, 49 EP
part C pins: 8 RF5G, 10 RF2G4, 18 OSC_OUT, 19 OSC_IN

## Socket_UFQFPN48_TypeH
designator U?
part A pins: 1 PB12/VSSSMPS, 2 PB11/VDDSMPS, 3 PA8/VLXSMPS, 4 PA7/PB12, 5 PA6/PA8, 6 VDDA/PA7, 7 PA5/PA6, 8 PA3/VDDA, 9 PB10/PA5, 10 PA2, 12 PA1, 14 PD9, 15 PD8, 16 PD7-OTG_HSDM, 17 PD6-OTG_HSDP, 18 PB8, 19 PC15-OSC32_OUT, 20 PC14-OSC32_IN, 21 PC13, 23 PB4(NJRST), 24 PB3-SWO, 25 PA15, 26 PA14-SWCLK, 27 PA13-SWDIO, 28 PA12, 29 PA11, 30 PB2, 31 PB1, 32 PB0, 33 PB15, 34 PH3-BOOT0, 36 NRST, 40 OSC_OUT/VDDRF, 41 OSC_IN/OSC_OUT, 42 VDDRFPA/OSC_IN, 45 PA10/VDD11, 46 PA9/PA10, 47 PB14/PA9, 48 PB13/PB14
part B pins: 11 VDD, 13 VDDUSB, 22 VDD, 35 VDD, 37 RF, 38 VDDHPA, 39 VDDRF/VDDANA, 43 VDD/VDDRFPA, 44 VCAP/VDD, 49 VSS

## Socket_UFQFPN48_TypeI
designator U?
part A pins: 1 PB12/VSSSMPS, 3 PA8/VLXSMPS, 4 PA7/PB12, 5 PA6/PA8(MCO), 6 PA7/VDDA, 7 PA5/PA6, 9 PA5/NC, 10 PA2, 12 PA1, 14 PB9, 15 PB8, 16 PC15-OSC_OUT, 17 PC14-OSC32_IN, 18 PC13, 19 NC, 20 PB6, 21 PB5, 23 PB4(NJTRST), 24 PB3-SWO, 25 PA15, 26 PA14-SWCLK, 27 PA13-SWDIO, 28 PA12, 29 PA11, 30 PB2, 31 NC, 32 NC, 33 PB15, 34 PH3-BOOT0, 36 NRST, 37 RF, 40 OSC_OUT/VDDRF, 41 OSC_IN/OSC_OUT, 42 OSC_IN/VDDRFPA, 45 PA10/VDD11, 46 PA9/PA10, 47 PA9/NC, 48 NC
part B pins: 2 VDDSMPS/NC, 8 VDDA/NC, 11 VDD, 13 VDDUSB, 22 VDD, 35 VDD, 38 VDDHPA, 39 VDDANA/VDDRF, 43 VDD/VDDRFPA, 44 VDD/VCAP, 49 VSS

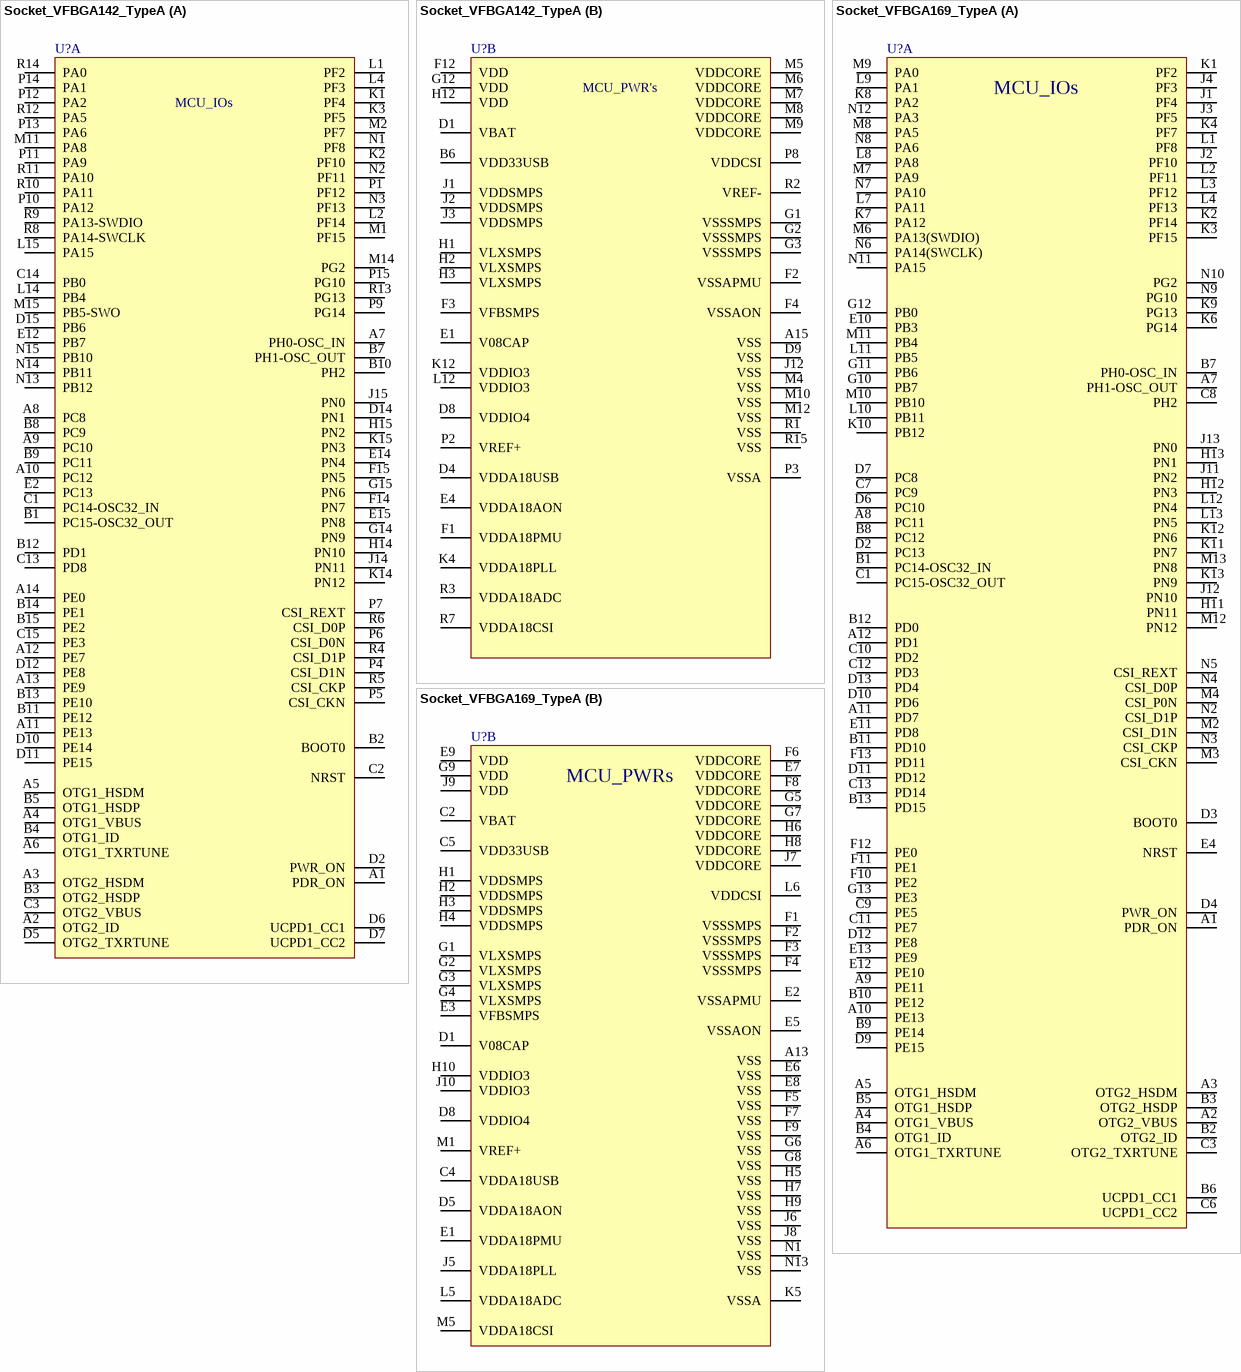
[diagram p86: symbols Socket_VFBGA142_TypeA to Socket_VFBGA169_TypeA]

## Socket_VFBGA142_TypeA
designator U?
part A pins: A1 PDR_ON, A2 OTG2_ID, A3 OTG2_HSDM, A4 OTG1_VBUS, A5 OTG1_HSDM, A6 OTG1_TXRTUNE, A7 PH0-OSC_IN, A8 PC8, A9 PC10, A10 PC12, A11 PE13, A12 PE7, A13 PE9, A14 PE0, B1 PC15-OSC32_OUT, B2 BOOT0, B3 OTG2_HSDP, B4 OTG1_ID, B5 OTG1_HSDP, B7 PH1-OSC_OUT, B8 PC9, B9 PC11, B10 PH2, B11 PE12, B12 PD1, B13 PE10, B14 PE1, B15 PE2, C1 PC14-OSC32_IN, C2 NRST, C3 OTG2_VBUS, C13 PD8, C14 PB0, C15 PE3, D2 PWR_ON, D5 OTG2_TXRTUNE, D6 UCPD1_CC1, D7 UCPD1_CC2, D10 PE14, D11 PE15, D12 PE8, D14 PN1, D15 PB6, E2 PC13, E12 PB7, E14 PN4, E15 PN8, F14 PN7, F15 PN5, G14 PN9, G15 PN6, H14 PN10, H15 PN2, J14 PN11, J15 PN0, K1 PF4, K2 PF10, K3 PF5, K14 PN12, K15 PN3, L1 PF2, L2 PF14, L4 PF3, L14 PB4, L15 PA15, M1 PF15, M2 PF7, M11 PA8, M14 PG2, M15 PB5-SWO, N1 PF8, N2 PF11, N3 PF13, N13 PB12, N14 PB11, N15 PB10, P1 PF12, P4 CSI_D1N, P5 CSI_CKN, P6 CSI_D0N, P7 CSI_REXT, P9 PG14, P10 PA12, P11 PA9, P12 PA2, P13 PA6, P14 PA1, P15 PG10, R4 CSI_D1P, R5 CSI_CKP, R6 CSI_D0P, R8 PA14-SWCLK, R9 PA13-SWDIO, R10 PA11, R11 PA10, R12 PA5, R13 PG13, R14 PA0
part B pins: A15 VSS, B6 VDD33USB, D1 VBAT, D4 VDDA18USB, D8 VDDIO4, D9 VSS, E1 V08CAP, E4 VDDA18AON, F1 VDDA18PMU, F2 VSSAPMU, F3 VFBSMPS, F4 VSSAON, F12 VDD, G1 VSSSMPS, G2 VSSSMPS, G3 VSSSMPS, G12 VDD, H1 VLXSMPS, H2 VLXSMPS, H3 VLXSMPS, H12 VDD, J1 VDDSMPS, J2 VDDSMPS, J3 VDDSMPS, J12 VSS, K4 VDDA18PLL, K12 VDDIO3, L12 VDDIO3, M4 VSS, M5 VDDCORE, M6 VDDCORE, M7 VDDCORE, M8 VDDCORE, M9 VDDCORE, M10 VSS, M12 VSS, P2 VREF+, P3 VSSA, P8 VDDCSI, R1 VSS, R2 VREF-, R3 VDDA18ADC, R7 VDDA18CSI, R15 VSS

## Socket_VFBGA169_TypeA
designator U?
part A pins: A1 PDR_ON, A2 OTG2_VBUS, A3 OTG2_HSDM, A4 OTG1_VBUS, A5 OTG1_HSDM, A6 OTG1_TXRTUNE, A7 PH1-OSC_OUT, A8 PC11, A9 PE11, A10 PE13, A11 PD7, A12 PD1, B1 PC14-OSC32_IN, B2 OTG2_ID, B3 OTG2_HSDP, B4 OTG1_ID, B5 OTG1_HSDP, B6 UCPD1_CC1, B7 PH0-OSC_IN, B8 PC12, B9 PE14, B10 PE12, B11 PD10, B12 PD0, B13 PD15, C1 PC15-OSC32_OUT, C3 OTG2_TXRTUNE, C6 UCPD1_CC2, C7 PC9, C8 PH2, C9 PE5, C10 PD2, C11 PE7, C12 PD3, C13 PD14, D2 PC13, D3 BOOT0, D4 PWR_ON, D6 PC10, D7 PC8, D9 PE15, D10 PD6, D11 PD12, D12 PE8, D13 PD4, E4 NRST, E10 PB3, E11 PD8, E12 PE10, E13 PE9, F10 PE2, F11 PE1, F12 PE0, F13 PD11, G10 PB7, G11 PB6, G12 PB0, G13 PE3, H11 PN11, H12 PN3, H13 PN1, J1 PF4, J2 PF10, J3 PF5, J4 PF3, J11 PN2, J12 PN10, J13 PN0, K1 PF2, K2 PF14, K3 PF15, K4 PF7, K6 PG14, K7 PA12, K8 PA2, K9 PG13, K10 PB12, K11 PN7, K12 PN6, K13 PN9, L1 PF8, L2 PF11, L3 PF12, L4 PF13, L7 PA11, L8 PA8, L9 PA1, L10 PB11, L11 PB5, L12 PN4, L13 PN5, M2 CSI_D1N, M3 CSI_CKN, M4 CSI_P0N, M6 PA13(SWDIO), M7 PA9, M8 PA5, M9 PA0, M10 PB10, M11 PB4, M12 PN12, M13 PN8, N2 CSI_D1P, N3 CSI_CKP, N4 CSI_D0P, N5 CSI_REXT, N6 PA14(SWCLK), N7 PA10, N8 PA6, N9 PG10, N10 PG2, N11 PA15, N12 PA3
part B pins: A13 VSS, C2 VBAT, C4 VDDA18USB, C5 VDD33USB, D1 V08CAP, D5 VDDA18AON, D8 VDDIO4, E1 VDDA18PMU, E2 VSSAPMU, E3 VFBSMPS, E5 VSSAON, E6 VSS, E7 VDDCORE, E8 VSS, E9 VDD, F1 VSSSMPS, F2 VSSSMPS, F3 VSSSMPS, F4 VSSSMPS, F5 VSS, F6 VDDCORE, F7 VSS, F8 VDDCORE, F9 VSS, G1 VLXSMPS, G2 VLXSMPS, G3 VLXSMPS, G4 VLXSMPS, G5 VDDCORE, G6 VSS, G7 VDDCORE, G8 VSS, G9 VDD, H1 VDDSMPS, H2 VDDSMPS, H3 VDDSMPS, H4 VDDSMPS, H5 VSS, H6 VDDCORE, H7 VSS, H8 VDDCORE, H9 VSS, H10 VDDIO3, J5 VDDA18PLL, J6 VSS, J7 VDDCORE, J8 VSS, J9 VDD, J10 VDDIO3, K5 VSSA, L5 VDDA18ADC, L6 VDDCSI, M1 VREF+, M5 VDDA18CSI, N1 VSS, N13 VSS

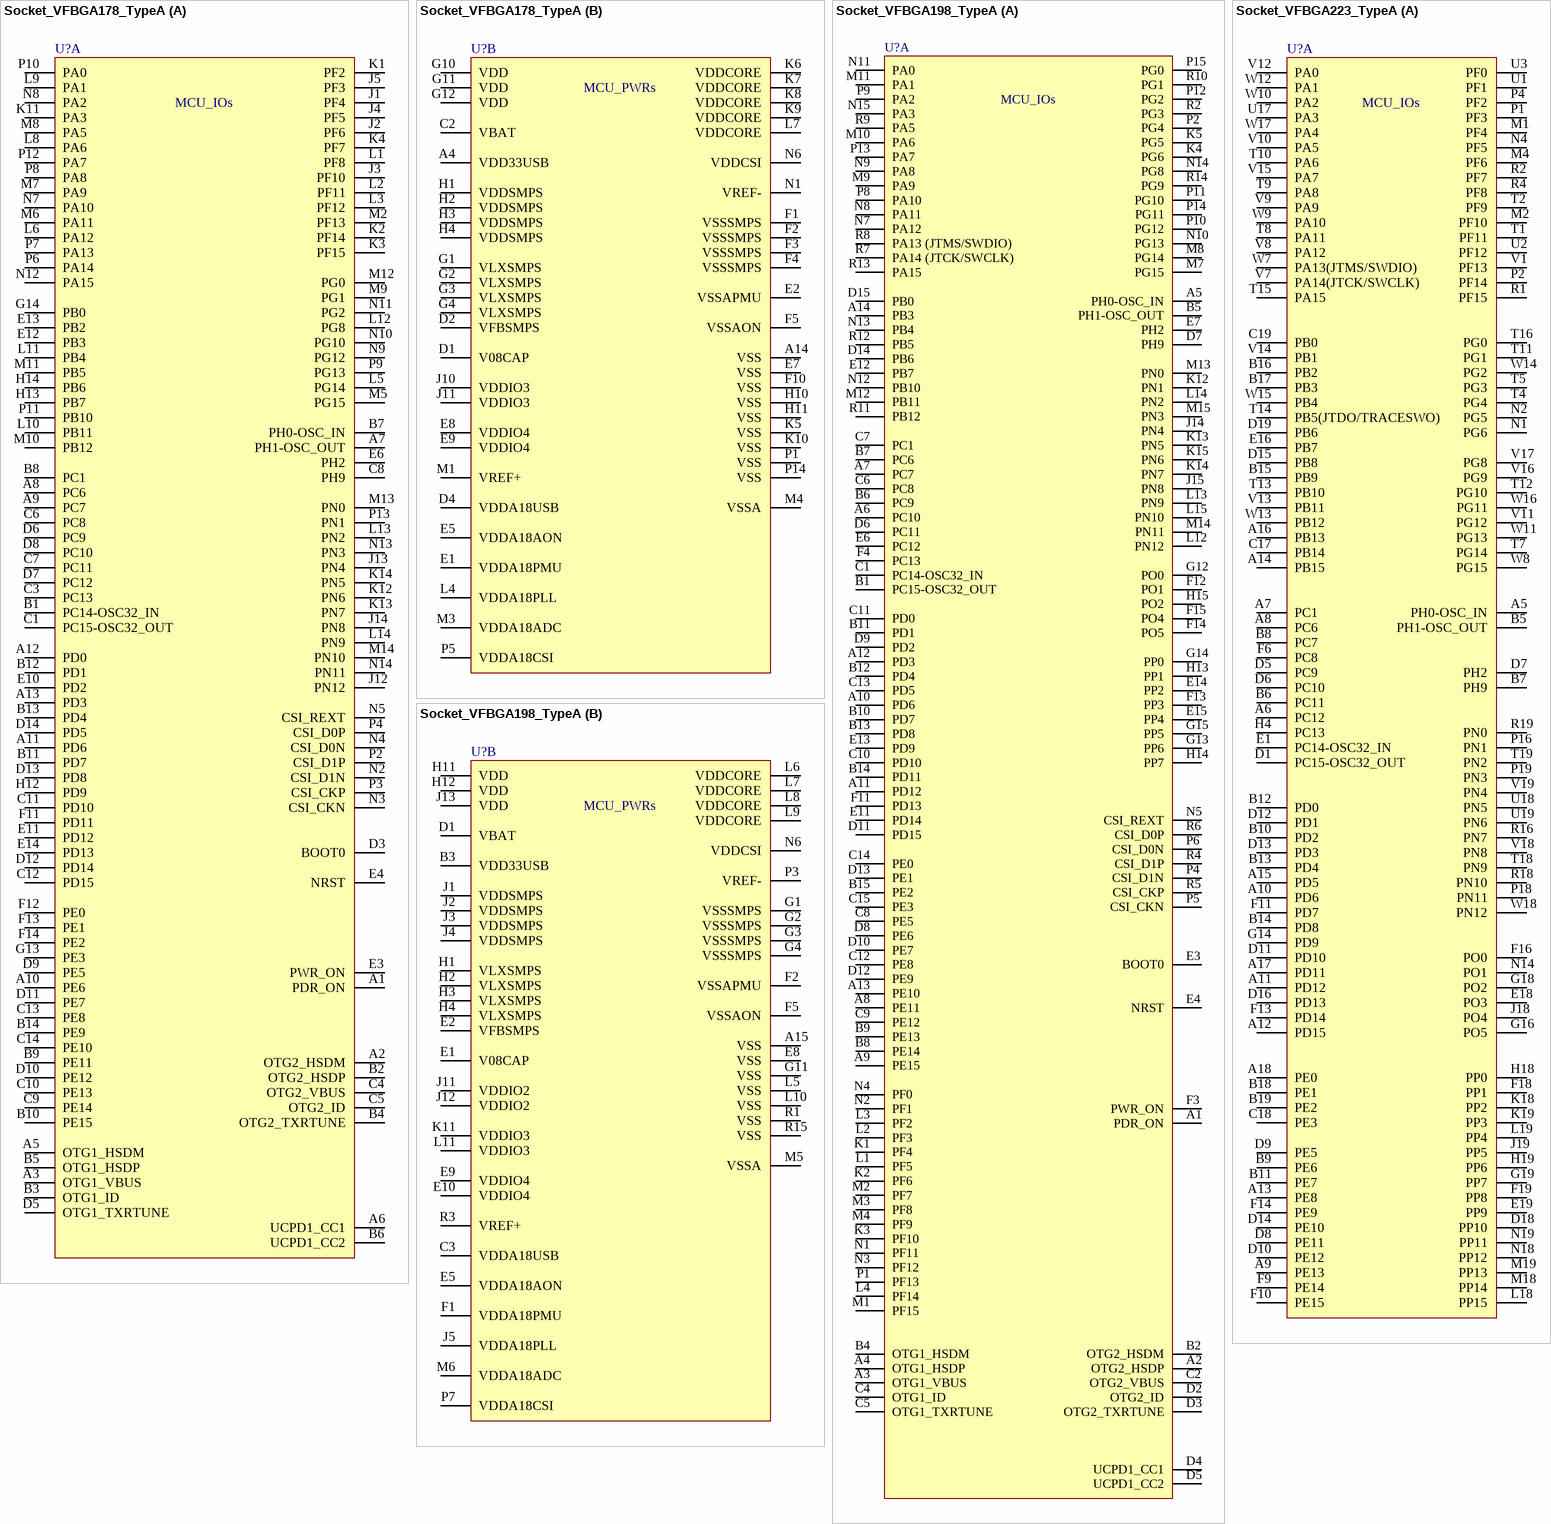
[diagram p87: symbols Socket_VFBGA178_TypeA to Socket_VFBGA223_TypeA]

## Socket_VFBGA178_TypeA
designator U?
part A pins: A1 PDR_ON, A2 OTG2_HSDM, A3 OTG1_VBUS, A5 OTG1_HSDM, A6 UCPD1_CC1, A7 PH1-OSC_OUT, A8 PC6, A9 PC7, A10 PE6, A11 PD6, A12 PD0, A13 PD3, B1 PC14-OSC32_IN, B2 OTG2_HSDP, B3 OTG1_ID, B4 OTG2_TXRTUNE, B5 OTG1_HSDP, B6 UCPD1_CC2, B7 PH0-OSC_IN, B8 PC1, B9 PE11, B10 PE15, B11 PD7, B12 PD1, B13 PD4, B14 PE9, C1 PC15-OSC32_OUT, C3 PC13, C4 OTG2_VBUS, C5 OTG2_ID, C6 PC8, C7 PC11, C8 PH9, C9 PE14, C10 PE13, C11 PD10, C12 PD15, C13 PE8, C14 PE10, D3 BOOT0, D5 OTG1_TXRTUNE, D6 PC9, D7 PC12, D8 PC10, D9 PE5, D10 PE12, D11 PE7, D12 PD14, D13 PD8, D14 PD5, E3 PWR_ON, E4 NRST, E6 PH2, E10 PD2, E11 PD12, E12 PB3, E13 PB2, E14 PD13, F11 PD11, F12 PE0, F13 PE1, F14 PE2, G13 PE3, G14 PB0, H12 PD9, H13 PB7, H14 PB6, J1 PF4, J2 PF6, J3 PF10, J4 PF5, J5 PF3, J12 PN12, J13 PN4, J14 PN8, K1 PF2, K2 PF14, K3 PF15, K4 PF7, K11 PA3, K12 PN6, K13 PN7, K14 PN5, L1 PF8, L2 PF11, L3 PF12, L5 PG14, L6 PA12, L8 PA6, L9 PA1, L10 PB11, L11 PB4, L12 PG8, L13 PN2, L14 PN9, M2 PF13, M5 PG15, M6 PA11, M7 PA9, M8 PA5, M9 PG1, M10 PB12, M11 PB5, M12 PG0, M13 PN0, M14 PN10, N2 CSI_D1N, N3 CSI_CKN, N4 CSI_D0N, N5 CSI_REXT, N7 PA10, N8 PA2, N9 PG12, N10 PG10, N11 PG2, N12 PA15, N13 PN3, N14 PN11, P2 CSI_D1P, P3 CSI_CKP, P4 CSI_D0P, P6 PA14, P7 PA13, P8 PA8, P9 PG13, P10 PA0, P11 PB10, P12 PA7, P13 PN1
part B pins: A4 VDD33USB, A14 VSS, C2 VBAT, D1 V08CAP, D2 VFBSMPS, D4 VDDA18USB, E1 VDDA18PMU, E2 VSSAPMU, E5 VDDA18AON, E7 VSS, E8 VDDIO4, E9 VDDIO4, F1 VSSSMPS, F2 VSSSMPS, F3 VSSSMPS, F4 VSSSMPS, F5 VSSAON, F10 VSS, G1 VLXSMPS, G2 VLXSMPS, G3 VLXSMPS, G4 VLXSMPS, G10 VDD, G11 VDD, G12 VDD, H1 VDDSMPS, H2 VDDSMPS, H3 VDDSMPS, H4 VDDSMPS, H10 VSS, H11 VSS, J10 VDDIO3, J11 VDDIO3, K5 VSS, K6 VDDCORE, K7 VDDCORE, K8 VDDCORE, K9 VDDCORE, K10 VSS, L4 VDDA18PLL, L7 VDDCORE, M1 VREF+, M3 VDDA18ADC, M4 VSSA, N1 VREF-, N6 VDDCSI, P1 VSS, P5 VDDA18CSI, P14 VSS

## Socket_VFBGA198_TypeA
designator U?
part A pins: A1 PDR_ON, A2 OTG2_HSDP, A3 OTG1_VBUS, A4 OTG1_HSDP, A5 PH0-OSC_IN, A6 PC10, A7 PC7, A8 PE11, A9 PE15, A10 PD6, A11 PD12, A12 PD3, A13 PE10, A14 PB3, B1 PC15-OSC32_OUT, B2 OTG2_HSDM, B4 OTG1_HSDM, B5 PH1-OSC_OUT, B6 PC9, B7 PC6, B8 PE14, B9 PE13, B10 PD7, B11 PD1, B12 PD4, B13 PD8, B14 PD11, B15 PE2, C1 PC14-OSC32_IN, C2 OTG2_VBUS, C4 OTG1_ID, C5 OTG1_TXRTUNE, C6 PC8, C7 PC1, C8 PE5, C9 PE12, C10 PD10, C11 PD0, C12 PE8, C13 PD5, C14 PE0, C15 PE3, D2 OTG2_ID, D3 OTG2_TXRTUNE, D4 UCPD1_CC1, D5 UCPD1_CC2, D6 PC11, D7 PH9, D8 PE6, D9 PD2, D10 PE7, D11 PD15, D12 PE9, D13 PE1, D14 PB6, D15 PB0, E3 BOOT0, E4 NRST, E6 PC12, E7 PH2, E11 PD14, E12 PB7, E13 PD9, E14 PP2, E15 PP4, F3 PWR_ON, F4 PC13, F11 PD13, F12 PO1, F13 PP3, F14 PO5, F15 PO4, G12 PO0, G13 PP6, G14 PP0, G15 PP5, H13 PP1, H14 PP7, H15 PO2, J14 PN4, J15 PN8, K1 PF4, K2 PF6, K3 PF10, K4 PG6, K5 PG5, K12 PN1, K13 PN5, K14 PN7, K15 PN6, L1 PF5, L2 PF3, L3 PF2, L4 PF14, L12 PN12, L13 PN9, L14 PN2, L15 PN10, M1 PF15, M2 PF7, M3 PF8, M4 PF9, M7 PG15, M8 PG14, M9 PA9, M10 PA6, M11 PA1, M12 PB11, M13 PN0, M14 PN11, M15 PN3, N1 PF11, N2 PF1, N3 PF12, N4 PF0, N5 CSI_REXT, N7 PA12, N8 PA11, N9 PA8, N10 PG13, N11 PA0, N12 PB10, N13 PB4, N14 PG8, N15 PA3, P1 PF13, P2 PG4, P4 CSI_D1N, P5 CSI_CKN, P6 CSI_D0N, P8 PA10, P9 PA2, P10 PG12, P11 PG10, P12 PG2, P13 PA7, P14 PG11, P15 PG0, R2 PG3, R4 CSI_D1P, R5 CSI_CKP, R6 CSI_D0P, R7 PA14 (JTCK/SWCLK), R8 PA13 (JTMS/SWDIO), R9 PA5, R10 PG1, R11 PB12, R12 PB5, R13 PA15, R14 PG9
part B pins: A15 VSS, B3 VDD33USB, C3 VDDA18USB, D1 VBAT, E1 V08CAP, E2 VFBSMPS, E5 VDDA18AON, E8 VSS, E9 VDDIO4, E10 VDDIO4, F1 VDDA18PMU, F2 VSSAPMU, F5 VSSAON, G1 VSSSMPS, G2 VSSSMPS, G3 VSSSMPS, G4 VSSSMPS, G11 VSS, H1 VLXSMPS, H2 VLXSMPS, H3 VLXSMPS, H4 VLXSMPS, H11 VDD, H12 VDD, J1 VDDSMPS, J2 VDDSMPS, J3 VDDSMPS, J4 VDDSMPS, J5 VDDA18PLL, J11 VDDIO2, J12 VDDIO2, J13 VDD, K11 VDDIO3, L5 VSS, L6 VDDCORE, L7 VDDCORE, L8 VDDCORE, L9 VDDCORE, L10 VSS, L11 VDDIO3, M5 VSSA, M6 VDDA18ADC, N6 VDDCSI, P3 VREF-, P7 VDDA18CSI, R1 VSS, R3 VREF+, R15 VSS

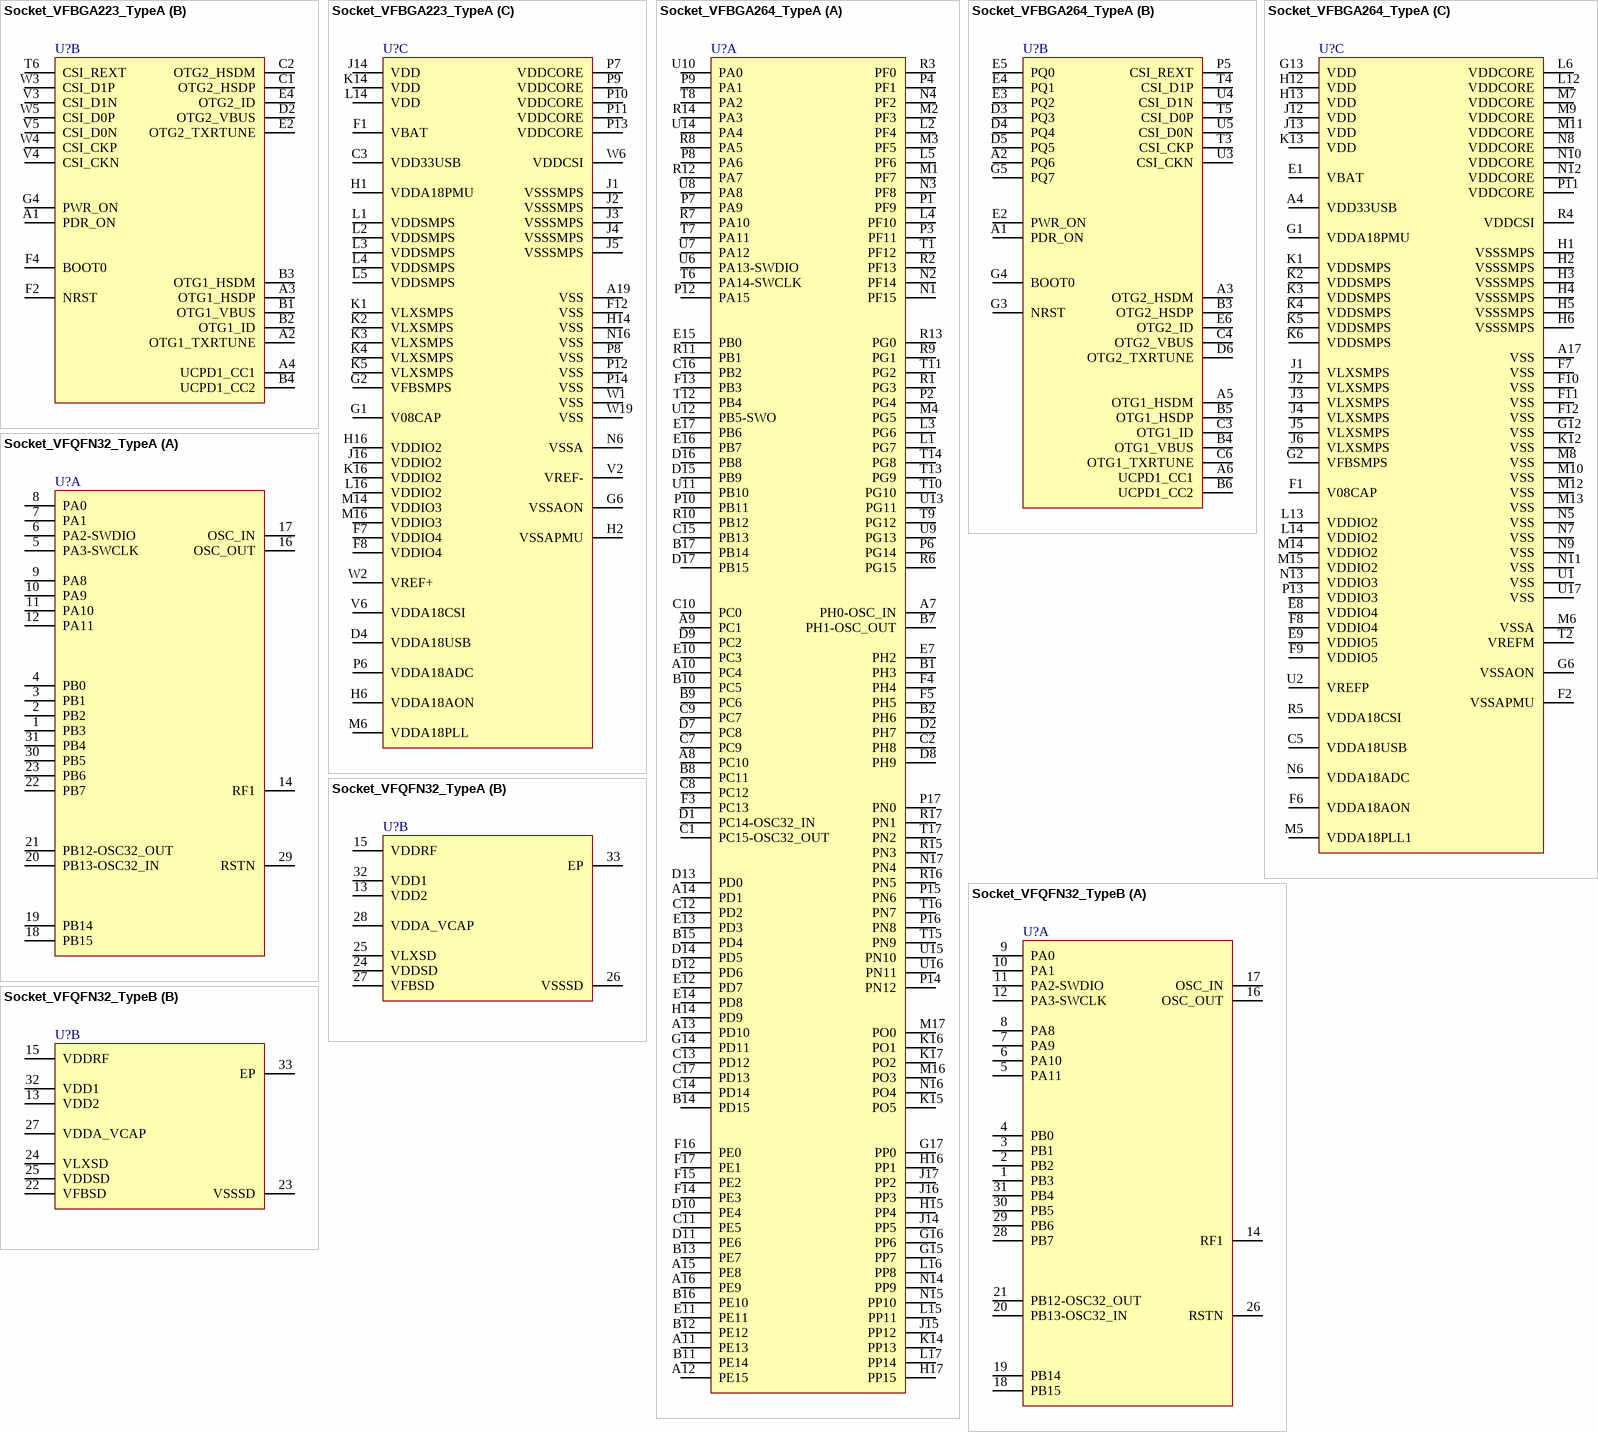
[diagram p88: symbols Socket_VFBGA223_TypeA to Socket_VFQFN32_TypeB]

## Socket_VFBGA223_TypeA
designator U?
part A pins: A5 PH0-OSC_IN, A6 PC12, A7 PC1, A8 PC6, A9 PE13, A10 PD6, A11 PD12, A12 PD15, A13 PE8, A14 PB15, A15 PD5, A16 PB13, A17 PD11, A18 PE0, B5 PH1-OSC_OUT, B6 PC11, B7 PH9, B8 PC7, B9 PE6, B10 PD2, B11 PE7, B12 PD0, B13 PD4, B14 PD8, B15 PB9, B16 PB2, B17 PB3, B18 PE1, B19 PE2, C17 PB14, C18 PE3, C19 PB0, D1 PC15-OSC32_OUT, D5 PC9, D6 PC10, D7 PH2, D8 PE11, D9 PE5, D10 PE12, D11 PD10, D12 PD1, D13 PD3, D14 PE10, D15 PB8, D16 PD13, D18 PP10, D19 PB6, E1 PC14-OSC32_IN, E16 PB7, E18 PO3, E19 PP9, F6 PC8, F9 PE14, F10 PE15, F11 PD7, F13 PD14, F14 PE9, F16 PO0, F18 PP1, F19 PP8, G14 PD9, G16 PO5, G18 PO2, G19 PP7, H4 PC13, H18 PP0, H19 PP6, J18 PO4, J19 PP5, K18 PP2, K19 PP3, L18 PP15, L19 PP4, M1 PF4, M2 PF10, M4 PF6, M18 PP14, M19 PP13, N1 PG6, N2 PG5, N4 PF5, N14 PO1, N18 PP12, N19 PP11, P1 PF3, P2 PF14, P4 PF2, P16 PN1, P18 PN11, P19 PN3, R1 PF15, R2 PF7, R4 PF8, R16 PN7, R18 PN10, R19 PN0, T1 PF11, T2 PF9, T4 PG4, T5 PG3, T7 PG14, T8 PA11, T9 PA8, T10 PA6, T11 PG1, T12 PG10, T13 PB10, T14 PB5(JTDO/TRACESWO), T15 PA15, T16 PG0, T18 PN9, T19 PN2, U1 PF1, U2 PF12, U3 PF0, U17 PA3, U18 PN5, U19 PN6, V1 PF13, V7 PA14(JTCK/SWCLK), V8 PA12, V9 PA9, V10 PA5, V11 PG12, V12 PA0, V13 PB11, V14 PB1, V15 PA7, V16 PG9, V17 PG8, V18 PN8, V19 PN4, W7 PA13(JTMS/SWDIO), W8 PG15, W9 PA10, W10 PA2, W11 PG13, W12 PA1, W13 PB12, W14 PG2, W15 PB4, W16 PG11, W17 PA4, W18 PN12
part B pins: A1 PDR_ON, A2 OTG1_TXRTUNE, A3 OTG1_HSDP, A4 UCPD1_CC1, B1 OTG1_VBUS, B2 OTG1_ID, B3 OTG1_HSDM, B4 UCPD1_CC2, C1 OTG2_HSDP, C2 OTG2_HSDM, D2 OTG2_VBUS, E2 OTG2_TXRTUNE, E4 OTG2_ID, F2 NRST, F4 BOOT0, G4 PWR_ON, T6 CSI_REXT, V3 CSI_D1N, V4 CSI_CKN, V5 CSI_D0N, W3 CSI_D1P, W4 CSI_CKP, W5 CSI_D0P
part C pins: A19 VSS (power), C3 VDD33USB (power), D4 VDDA18USB (power) "pa", F1 VBAT (power) "pa", F7 VDDIO4 (power), F8 VDDIO4 (power), F12 VSS (power), G1 V08CAP, G2 VFBSMPS, G6 VSSAON (power), H1 VDDA18PMU (power), H2 VSSAPMU (power), H6 VDDA18AON (power), H14 VSS (power), H16 VDDIO2 (power), J1 VSSSMPS (power), J2 VSSSMPS (power), J3 VSSSMPS (power), J4 VSSSMPS (power), J5 VSSSMPS (power), J14 VDD (power), J16 VDDIO2, K1 VLXSMPS (power), K2 VLXSMPS (power), K3 VLXSMPS (power), K4 VLXSMPS (power), K5 VLXSMPS (power), K14 VDD (power), K16 VDDIO2 (power), L1 VDDSMPS (power) "pa", L2 VDDSMPS (power), L3 VDDSMPS (power), L4 VDDSMPS (power) "pa", L5 VDDSMPS (power), L14 VDD (power) "pa", L16 VDDIO2 (power), M6 VDDA18PLL (power) "pa", M14 VDDIO3 (power), M16 VDDIO3 (power), N6 VSSA (power), N16 VSS (power), P6 VDDA18ADC (power), P7 VDDCORE (power), P8 VSS (power), P9 VDDCORE (power), P10 VDDCORE (power), P11 VDDCORE (power), P12 VSS (power), P13 VDDCORE (power), P14 VSS (power), V2 VREF- (power), V6 VDDA18CSI (power), W1 VSS (power), W2 VREF+ (power), W6 VDDCSI (power), W19 VSS (power)

## Socket_VFBGA264_TypeA
designator U?
part A pins: A7 PH0-OSC_IN, A8 PC10, A9 PC1, A10 PC4, A11 PE13, A12 PE15, A13 PD10, A14 PD1, A15 PE8, A16 PE9, B1 PH3, B2 PH6, B7 PH1-OSC_OUT, B8 PC11, B9 PC6, B10 PC5, B11 PE14, B12 PE12, B13 PE7, B14 PD15, B15 PD4, B16 PE10, B17 PB14, C1 PC15-OSC32_OUT, C2 PH8, C7 PC9, C8 PC12, C9 PC7, C10 PC0, C11 PE5, C12 PD2, C13 PD12, C14 PD14, C15 PB13, C16 PB2, C17 PD13, D1 PC14-OSC32_IN, D2 PH7, D7 PC8, D8 PH9, D9 PC2, D10 PE4, D11 PE6, D12 PD6, D13 PD0, D14 PD5, D15 PB9, D16 PB8, D17 PB15, E7 PH2, E10 PC3, E11 PE11, E12 PD7, E13 PD3, E14 PD8, E15 PB0, E16 PB7, E17 PB6, F3 PC13, F4 PH4, F5 PH5, F13 PB3, F14 PE3, F15 PE2, F16 PE0, F17 PE1, G14 PD11, G15 PP7, G16 PP6, G17 PP0, H14 PD9, H15 PP4, H16 PP1, H17 PP15, J14 PP5, J15 PP12, J16 PP3, J17 PP2, K14 PP13, K15 PO5, K16 PO1, K17 PO2, L1 PG7, L2 PF4, L3 PG6, L4 PF10, L5 PF6, L15 PP11, L16 PP8, L17 PP14, M1 PF7, M2 PF3, M3 PF5, M4 PG5, M16 PO3, M17 PO0, N1 PF15, N2 PF14, N3 PF8, N4 PF2, N14 PP9, N15 PP10, N16 PO4, N17 PN4, P1 PF9, P2 PG4, P3 PF11, P4 PF1, P6 PG14, P7 PA9, P8 PA6, P9 PA1, P10 PB11, P12 PA15, P14 PN12, P15 PN6, P16 PN8, P17 PN0, R1 PG3, R2 PF13, R3 PF0, R6 PG15, R7 PA10, R8 PA5, R9 PG1, R10 PB12, R11 PB1, R12 PA7, R13 PG0, R14 PA3, R15 PN3, R16 PN5, R17 PN1, T1 PF12, T6 PA14-SWCLK, T7 PA11, T8 PA2, T9 PG12, T10 PG10, T11 PG2, T12 PB4, T13 PG9, T14 PG8, T15 PN9, T16 PN7, T17 PN2, U6 PA13-SWDIO, U7 PA12, U8 PA8, U9 PG13, U10 PA0, U11 PB10, U12 PB5-SWO, U13 PG11, U14 PA4, U15 PN10, U16 PN11
part B pins: A1 PDR_ON, A2 PQ6, A3 OTG2_HSDM, A5 OTG1_HSDM, A6 UCPD1_CC1, B3 OTG2_HSDP, B4 OTG1_VBUS, B5 OTG1_HSDP, B6 UCPD1_CC2, C3 OTG1_ID, C4 OTG2_VBUS, C6 OTG1_TXRTUNE, D3 PQ3, D4 PQ4, D5 PQ5, D6 OTG2_TXRTUNE, E2 PWR_ON, E3 PQ2, E4 PQ1, E5 PQ0, E6 OTG2_ID, G3 NRST, G4 BOOT0, G5 PQ7, P5 CSI_REXT, T3 CSI_CKP, T4 CSI_D1P, T5 CSI_D0P, U3 CSI_CKN, U4 CSI_D1N, U5 CSI_D0N
part C pins: A4 VDD33USB, A17 VSS, C5 VDDA18USB, E1 VBAT, E8 VDDIO4, E9 VDDIO5, F1 V08CAP, F2 VSSAPMU, F6 VDDA18AON, F7 VSS, F8 VDDIO4, F9 VDDIO5, F10 VSS, F11 VSS, F12 VSS, G1 VDDA18PMU, G2 VFBSMPS, G6 VSSAON, G12 VSS, G13 VDD, H1 VSSSMPS, H2 VSSSMPS, H3 VSSSMPS, H4 VSSSMPS, H5 VSSSMPS, H6 VSSSMPS, H12 VDD, H13 VDD, J1 VLXSMPS, J2 VLXSMPS, J3 VLXSMPS, J4 VLXSMPS, J5 VLXSMPS, J6 VLXSMPS, J12 VDD, J13 VDD, K1 VDDSMPS, K2 VDDSMPS, K3 VDDSMPS, K4 VDDSMPS, K5 VDDSMPS, K6 VDDSMPS, K12 VSS, K13 VDD, L6 VDDCORE, L12 VDDCORE, L13 VDDIO2, L14 VDDIO2, M5 VDDA18PLL1, M6 VSSA, M7 VDDCORE, M8 VSS, M9 VDDCORE, M10 VSS, M11 VDDCORE, M12 VSS, M13 VSS, M14 VDDIO2, M15 VDDIO2, N5 VSS, N6 VDDA18ADC, N7 VSS, N8 VDDCORE, N9 VSS, N10 VDDCORE, N11 VSS, N12 VDDCORE, N13 VDDIO3, P11 VDDCORE, P13 VDDIO3, R4 VDDCSI, R5 VDDA18CSI, T2 VREFM, U1 VSS, U2 VREFP, U17 VSS

## Socket_VFQFN32_TypeA
designator U?
part A pins: 1 PB3, 2 PB2, 3 PB1, 4 PB0, 5 PA3-SWCLK, 6 PA2-SWDIO, 7 PA1, 8 PA0, 9 PA8, 10 PA9, 11 PA10, 12 PA11, 14 RF1, 16 OSC_OUT, 17 OSC_IN, 18 PB15, 19 PB14, 20 PB13-OSC32_IN, 21 PB12-OSC32_OUT, 22 PB7, 23 PB6, 29 RSTN, 30 PB5, 31 PB4
part B pins: 13 VDD2, 15 VDDRF, 24 VDDSD, 25 VLXSD, 26 VSSSD, 27 VFBSD, 28 VDDA_VCAP, 32 VDD1, 33 EP

## Socket_VFQFN32_TypeB
designator U?
part A pins: 1 PB3, 2 PB2, 3 PB1, 4 PB0, 5 PA11, 6 PA10, 7 PA9, 8 PA8, 9 PA0, 10 PA1, 11 PA2-SWDIO, 12 PA3-SWCLK, 14 RF1, 16 OSC_OUT, 17 OSC_IN, 18 PB15, 19 PB14, 20 PB13-OSC32_IN, 21 PB12-OSC32_OUT, 26 RSTN, 28 PB7, 29 PB6, 30 PB5, 31 PB4
part B pins: 13 VDD2, 15 VDDRF, 22 VFBSD, 23 VSSSD, 24 VLXSD, 25 VDDSD, 27 VDDA_VCAP, 32 VDD1, 33 EP

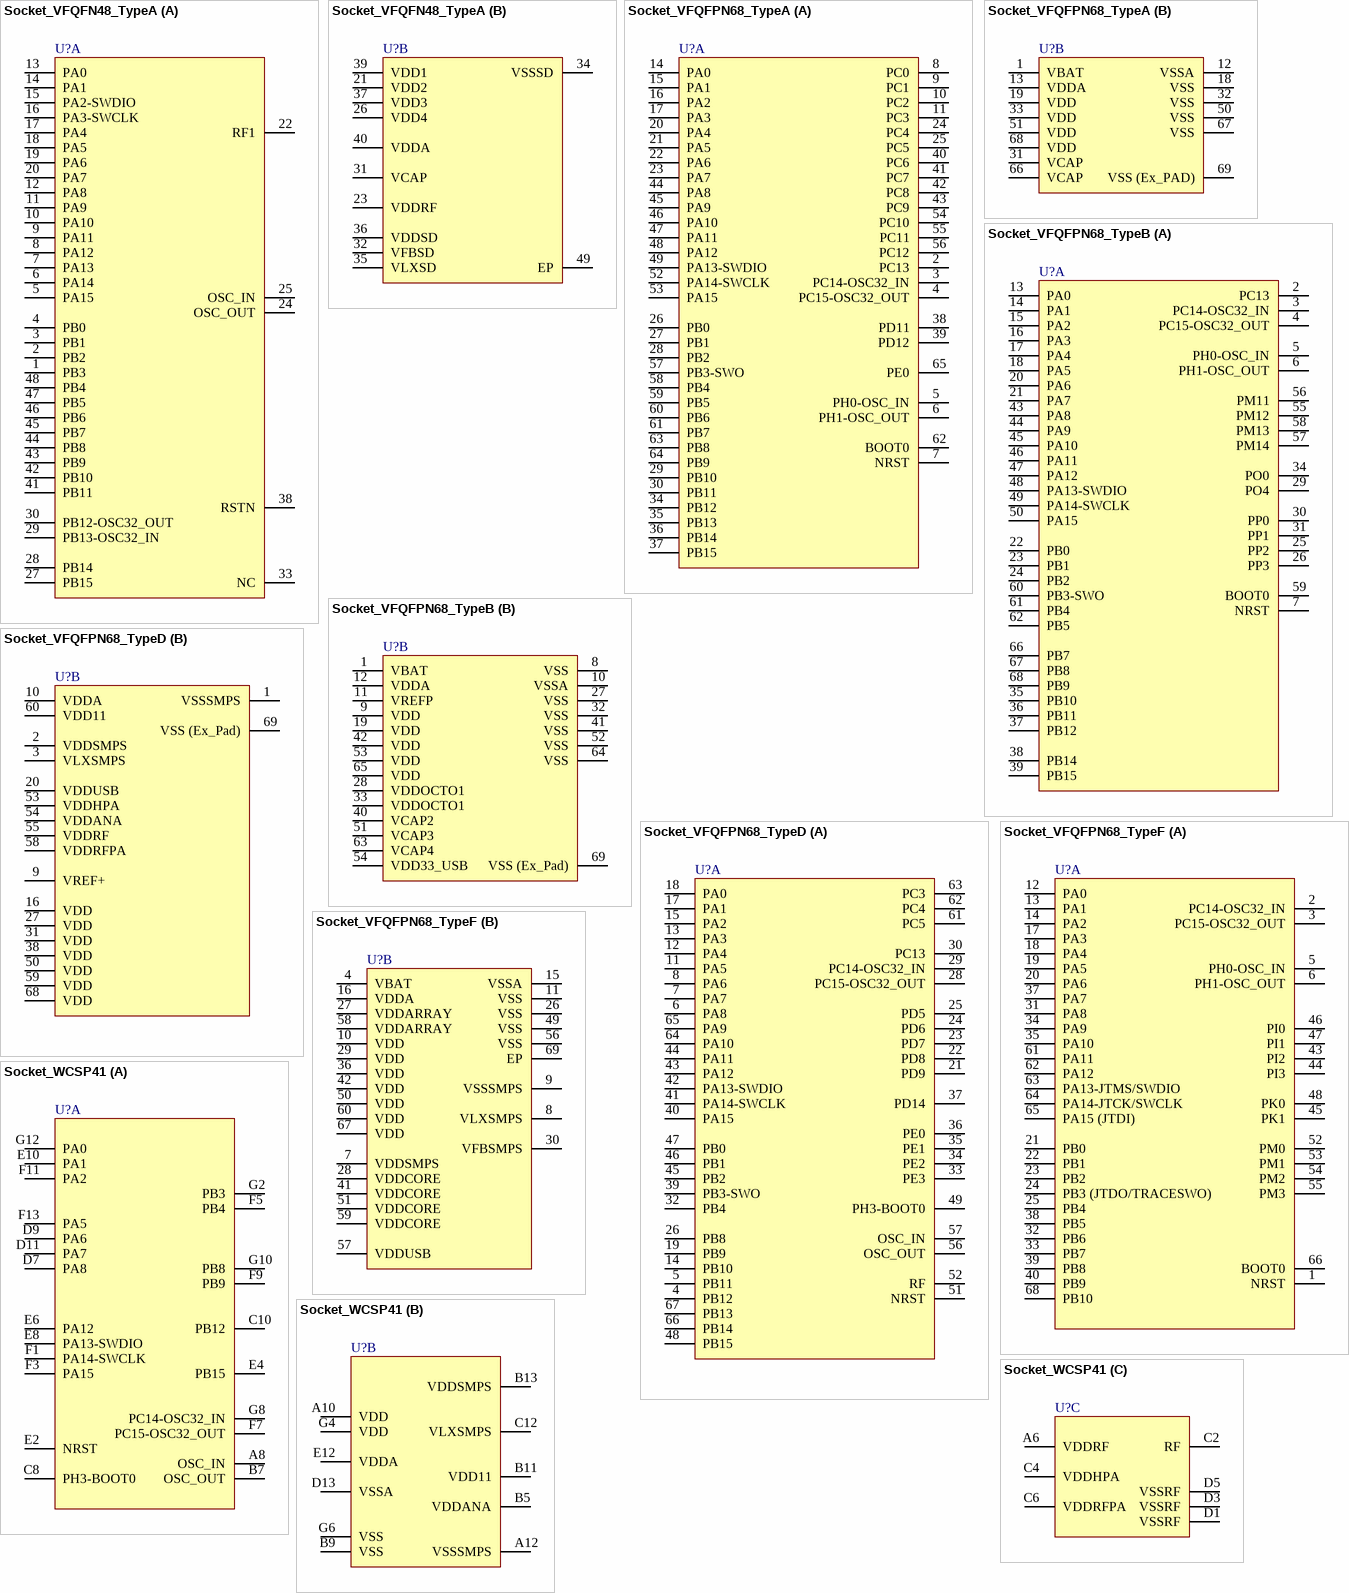
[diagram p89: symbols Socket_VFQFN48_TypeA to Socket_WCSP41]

## Socket_VFQFN48_TypeA
designator U?
part A pins: 1 PB3, 2 PB2, 3 PB1, 4 PB0, 5 PA15, 6 PA14, 7 PA13, 8 PA12, 9 PA11, 10 PA10, 11 PA9, 12 PA8, 13 PA0, 14 PA1, 15 PA2-SWDIO, 16 PA3-SWCLK, 17 PA4, 18 PA5, 19 PA6, 20 PA7, 22 RF1, 24 OSC_OUT, 25 OSC_IN, 27 PB15, 28 PB14, 29 PB13-OSC32_IN, 30 PB12-OSC32_OUT, 33 NC, 38 RSTN, 41 PB11, 42 PB10, 43 PB9, 44 PB8, 45 PB7, 46 PB6, 47 PB5, 48 PB4
part B pins: 21 VDD2, 23 VDDRF, 26 VDD4, 31 VCAP, 32 VFBSD, 34 VSSSD, 35 VLXSD, 36 VDDSD, 37 VDD3, 39 VDD1, 40 VDDA, 49 EP

## Socket_VFQFPN68_TypeA
designator U?
part A pins: 2 PC13, 3 PC14-OSC32_IN, 4 PC15-OSC32_OUT, 5 PH0-OSC_IN, 6 PH1-OSC_OUT, 7 NRST, 8 PC0, 9 PC1, 10 PC2, 11 PC3, 14 PA0, 15 PA1, 16 PA2, 17 PA3, 20 PA4, 21 PA5, 22 PA6, 23 PA7, 24 PC4, 25 PC5, 26 PB0, 27 PB1, 28 PB2, 29 PB10, 30 PB11, 34 PB12, 35 PB13, 36 PB14, 37 PB15, 38 PD11, 39 PD12, 40 PC6, 41 PC7, 42 PC8, 43 PC9, 44 PA8, 45 PA9, 46 PA10, 47 PA11, 48 PA12, 49 PA13-SWDIO, 52 PA14-SWCLK, 53 PA15, 54 PC10, 55 PC11, 56 PC12, 57 PB3-SWO, 58 PB4, 59 PB5, 60 PB6, 61 PB7, 62 BOOT0, 63 PB8, 64 PB9, 65 PE0
part B pins: 1 VBAT, 12 VSSA, 13 VDDA, 18 VSS, 19 VDD, 31 VCAP, 32 VSS, 33 VDD, 50 VSS, 51 VDD, 66 VCAP, 67 VSS, 68 VDD, 69 VSS (Ex_PAD)

## Socket_VFQFPN68_TypeB
designator U?
part A pins: 2 PC13, 3 PC14-OSC32_IN, 4 PC15-OSC32_OUT, 5 PH0-OSC_IN, 6 PH1-OSC_OUT, 7 NRST, 13 PA0, 14 PA1, 15 PA2, 16 PA3, 17 PA4, 18 PA5, 20 PA6, 21 PA7, 22 PB0, 23 PB1, 24 PB2, 25 PP2, 26 PP3, 29 PO4, 30 PP0, 31 PP1, 34 PO0, 35 PB10, 36 PB11, 37 PB12, 38 PB14, 39 PB15, 43 PA8, 44 PA9, 45 PA10, 46 PA11, 47 PA12, 48 PA13-SWDIO, 49 PA14-SWCLK, 50 PA15, 55 PM12, 56 PM11, 57 PM14, 58 PM13, 59 BOOT0, 60 PB3-SWO, 61 PB4, 62 PB5, 66 PB7, 67 PB8, 68 PB9
part B pins: 1 VBAT, 8 VSS, 9 VDD, 10 VSSA, 11 VREFP, 12 VDDA, 19 VDD, 27 VSS, 28 VDDOCTO1, 32 VSS, 33 VDDOCTO1, 40 VCAP2, 41 VSS, 42 VDD, 51 VCAP3, 52 VSS, 53 VDD, 54 VDD33_USB, 63 VCAP4, 64 VSS, 65 VDD, 69 VSS (Ex_Pad)

## Socket_VFQFPN68_TypeD
designator U?
part A pins: 4 PB12, 5 PB11, 6 PA8, 7 PA7, 8 PA6, 11 PA5, 12 PA4, 13 PA3, 14 PB10, 15 PA2, 17 PA1, 18 PA0, 19 PB9, 21 PD9, 22 PD8, 23 PD7, 24 PD6, 25 PD5, 26 PB8, 28 PC15-OSC32_OUT, 29 PC14-OSC32_IN, 30 PC13, 32 PB4, 33 PE3, 34 PE2, 35 PE1, 36 PE0, 37 PD14, 39 PB3-SWO, 40 PA15, 41 PA14-SWCLK, 42 PA13-SWDIO, 43 PA12, 44 PA11, 45 PB2, 46 PB1, 47 PB0, 48 PB15, 49 PH3-BOOT0, 51 NRST, 52 RF, 56 OSC_OUT, 57 OSC_IN, 61 PC5, 62 PC4, 63 PC3, 64 PA10, 65 PA9, 66 PB14, 67 PB13
part B pins: 1 VSSSMPS, 2 VDDSMPS, 3 VLXSMPS, 9 VREF+, 10 VDDA, 16 VDD, 20 VDDUSB, 27 VDD, 31 VDD, 38 VDD, 50 VDD, 53 VDDHPA, 54 VDDANA, 55 VDDRF, 58 VDDRFPA, 59 VDD, 60 VDD11, 68 VDD, 69 VSS (Ex_Pad)

## Socket_VFQFPN68_TypeF
designator U?
part A pins: 1 NRST, 2 PC14-OSC32_IN, 3 PC15-OSC32_OUT, 5 PH0-OSC_IN, 6 PH1-OSC_OUT, 12 PA0, 13 PA1, 14 PA2, 17 PA3, 18 PA4, 19 PA5, 20 PA6, 21 PB0, 22 PB1, 23 PB2, 24 PB3 (JTDO/TRACESWO), 25 PB4, 31 PA8, 32 PB6, 33 PB7, 34 PA9, 35 PA10, 37 PA7, 38 PB5, 39 PB8, 40 PB9, 43 PI2, 44 PI3, 45 PK1, 46 PI0, 47 PI1, 48 PK0, 52 PM0, 53 PM1, 54 PM2, 55 PM3, 61 PA11, 62 PA12, 63 PA13-JTMS/SWDIO, 64 PA14-JTCK/SWCLK, 65 PA15 (JTDI), 66 BOOT0, 68 PB10
part B pins: 4 VBAT, 7 VDDSMPS, 8 VLXSMPS, 9 VSSSMPS, 10 VDD, 11 VSS, 15 VSSA, 16 VDDA, 26 VSS, 27 VDDARRAY, 28 VDDCORE, 29 VDD, 30 VFBSMPS, 36 VDD, 41 VDDCORE, 42 VDD, 49 VSS, 50 VDD, 51 VDDCORE, 56 VSS, 57 VDDUSB, 58 VDDARRAY, 59 VDDCORE, 60 VDD, 67 VDD, 69 EP

## Socket_WCSP41
designator U?
part A pins: A8 OSC_IN, B7 OSC_OUT, C8 PH3-BOOT0, C10 PB12, D7 PA8, D9 PA6, D11 PA7, E2 NRST, E4 PB15, E6 PA12, E8 PA13-SWDIO, E10 PA1, F1 PA14-SWCLK, F3 PA15, F5 PB4, F7 PC15-OSC32_OUT, F9 PB9, F11 PA2, F13 PA5, G2 PB3, G8 PC14-OSC32_IN, G10 PB8, G12 PA0
part B pins: A10 VDD, A12 VSSSMPS, B5 VDDANA, B9 VSS, B11 VDD11, B13 VDDSMPS, C12 VLXSMPS, D13 VSSA, E12 VDDA, G4 VDD, G6 VSS
part C pins: A6 VDDRF, C2 RF, C4 VDDHPA, C6 VDDRFPA, D1 VSSRF, D3 VSSRF, D5 VSSRF

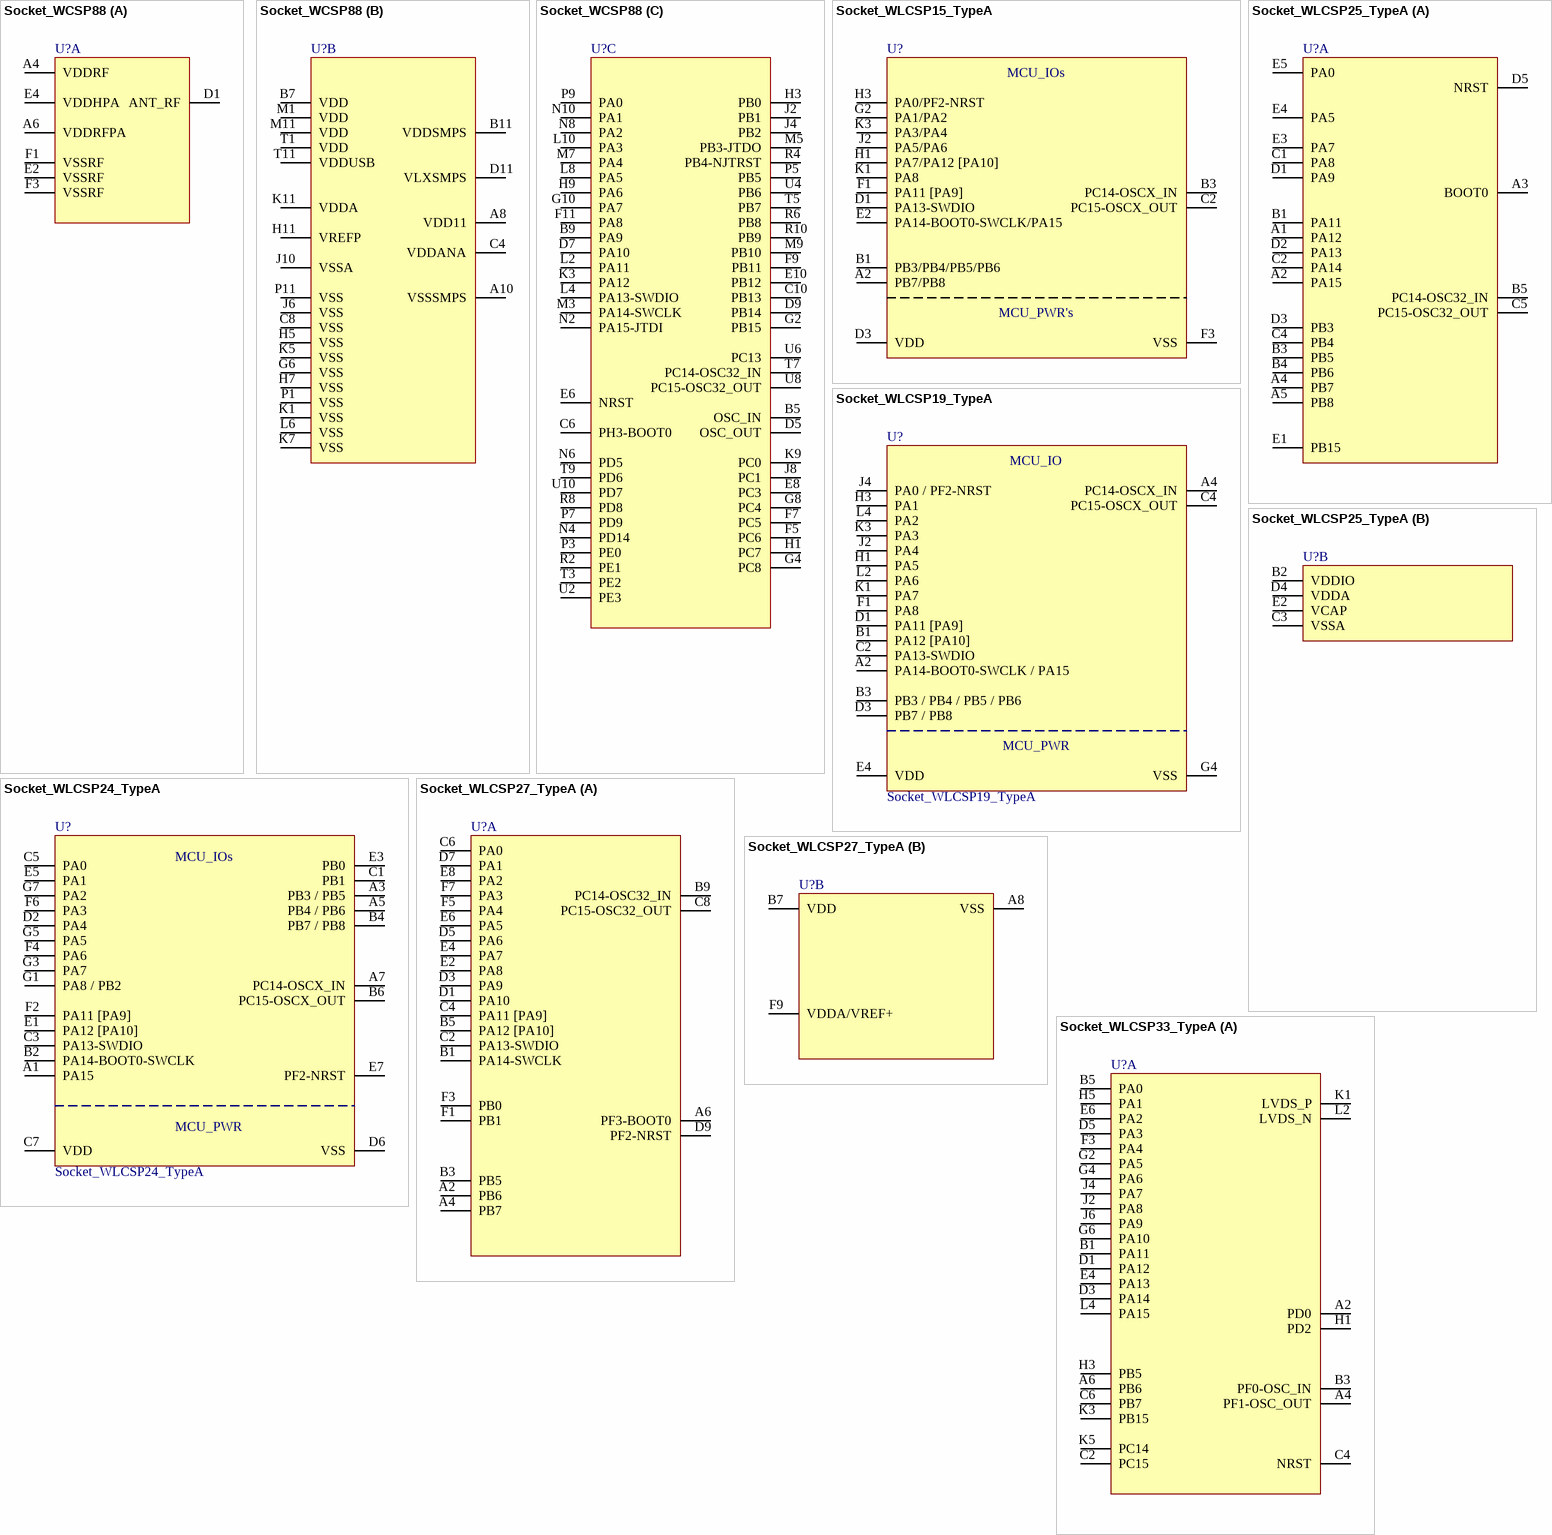
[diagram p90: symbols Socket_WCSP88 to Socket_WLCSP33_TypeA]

## Socket_WCSP88
designator U?
part A pins: A4 VDDRF, A6 VDDRFPA, D1 ANT_RF, E2 VSSRF, E4 VDDHPA, F1 VSSRF, F3 VSSRF
part B pins: A8 VDD11, A10 VSSSMPS, B7 VDD, B11 VDDSMPS, C4 VDDANA, C8 VSS, D11 VLXSMPS, G6 VSS, H5 VSS, H7 VSS, H11 VREFP, J6 VSS, J10 VSSA, K1 VSS, K5 VSS, K7 VSS, K11 VDDA, L6 VSS, M1 VDD, M11 VDD, P1 VSS, P11 VSS, T1 VDD, T11 VDDUSB
part C pins: B5 OSC_IN, B9 PA9, C6 PH3-BOOT0, C10 PB13, D5 OSC_OUT, D7 PA10, D9 PB14, E6 NRST, E8 PC3, E10 PB12, F5 PC6, F7 PC5, F9 PB11, F11 PA8, G2 PB15, G4 PC8, G8 PC4, G10 PA7, H1 PC7, H3 PB0, H9 PA6, J2 PB1, J4 PB2, J8 PC1, K3 PA12, K9 PC0, L2 PA11, L4 PA13-SWDIO, L8 PA5, L10 PA3, M3 PA14-SWCLK, M5 PB3-JTDO, M7 PA4, M9 PB10, N2 PA15-JTDI, N4 PD14, N6 PD5, N8 PA2, N10 PA1, P3 PE0, P5 PB5, P7 PD9, P9 PA0, R2 PE1, R4 PB4-NJTRST, R6 PB8, R8 PD8, R10 PB9, T3 PE2, T5 PB7, T7 PC14-OSC32_IN, T9 PD6, U2 PE3, U4 PB6, U6 PC13, U8 PC15-OSC32_OUT, U10 PD7

## Socket_WLCSP15_TypeA
designator U?
pins: A2 PB7/PB8, B1 PB3/PB4/PB5/PB6, B3 PC14-OSCX_IN, C2 PC15-OSCX_OUT, D1 PA13-SWDIO, D3 VDD, E2 PA14-BOOT0-SWCLK/PA15, F1 PA11 [PA9], F3 VSS, G2 PA1/PA2, H1 PA7/PA12 [PA10], H3 PA0/PF2-NRST, J2 PA5/PA6, K1 PA8, K3 PA3/PA4

## Socket_WLCSP19_TypeA
designator U?
pins: A2 PA14-BOOT0-SWCLK / PA15, A4 PC14-OSCX_IN, B1 PA12 [PA10], B3 PB3 / PB4 / PB5 / PB6, C2 PA13-SWDIO, C4 PC15-OSCX_OUT, D1 PA11 [PA9], D3 PB7 / PB8, E4 VDD, F1 PA8, G4 VSS, H1 PA5, H3 PA1, J2 PA4, J4 PA0 / PF2-NRST, K1 PA7, K3 PA3, L2 PA6, L4 PA2

## Socket_WLCSP24_TypeA
designator U?
pins: A1 PA15, A3 PB3 / PB5, A5 PB4 / PB6, A7 PC14-OSCX_IN, B2 PA14-BOOT0-SWCLK, B4 PB7 / PB8, B6 PC15-OSCX_OUT, C1 PB1, C3 PA13-SWDIO, C5 PA0, C7 VDD, D2 PA4, D6 VSS, E1 PA12 [PA10], E3 PB0, E5 PA1, E7 PF2-NRST, F2 PA11 [PA9], F4 PA6, F6 PA3, G1 PA8 / PB2, G3 PA7, G5 PA5, G7 PA2

## Socket_WLCSP25_TypeA
designator U?
part A pins: A1 PA12, A2 PA15, A3 BOOT0, A4 PB7, A5 PB8, B1 PA11, B3 PB5, B4 PB6, B5 PC14-OSC32_IN, C1 PA8, C2 PA14, C4 PB4, C5 PC15-OSC32_OUT, D1 PA9, D2 PA13, D3 PB3, D5 NRST, E1 PB15, E3 PA7, E4 PA5, E5 PA0
part B pins: B2 VDDIO, C3 VSSA, D4 VDDA, E2 VCAP

## Socket_WLCSP27_TypeA
designator U?
part A pins: A2 PB6, A4 PB7, A6 PF3-BOOT0, B1 PA14-SWCLK, B3 PB5, B5 PA12 [PA10], B9 PC14-OSC32_IN, C2 PA13-SWDIO, C4 PA11 [PA9], C6 PA0, C8 PC15-OSC32_OUT, D1 PA10, D3 PA9, D5 PA6, D7 PA1, D9 PF2-NRST, E2 PA8, E4 PA7, E6 PA5, E8 PA2, F1 PB1, F3 PB0, F5 PA4, F7 PA3
part B pins: A8 VSS, B7 VDD, F9 VDDA/VREF+

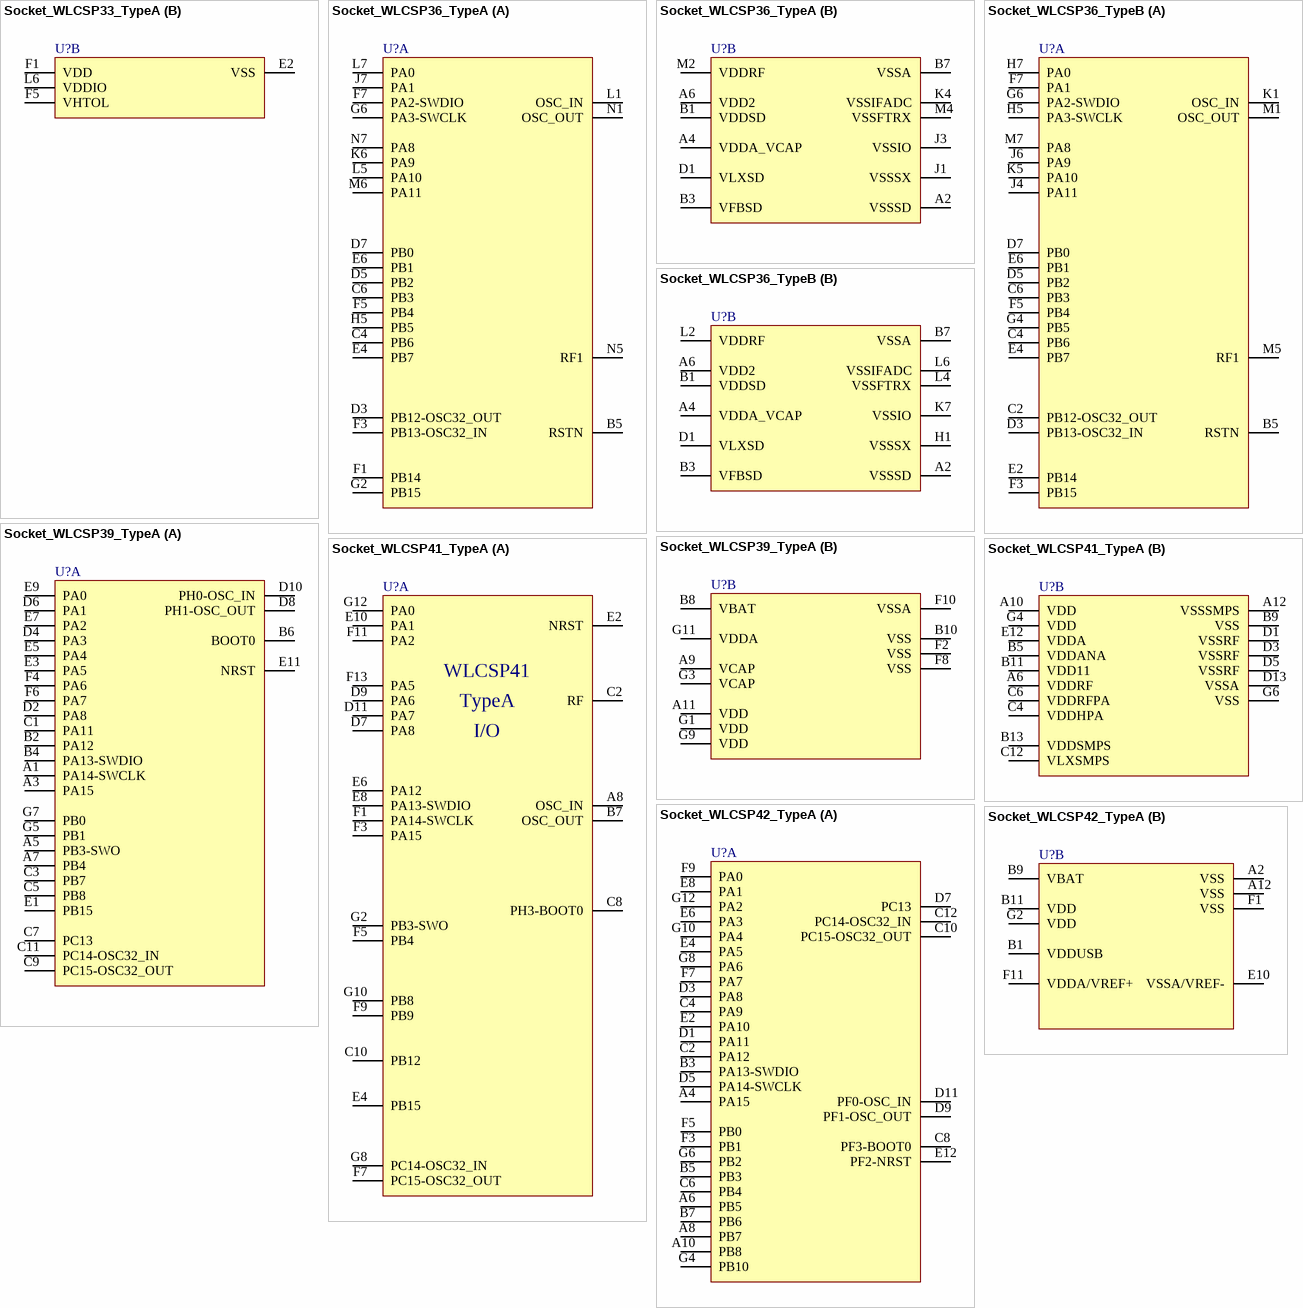
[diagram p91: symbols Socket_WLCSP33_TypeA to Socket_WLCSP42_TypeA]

## Socket_WLCSP33_TypeA
designator U?
part A pins: A2 PD0, A4 PF1-OSC_OUT, A6 PB6, B1 PA11, B3 PF0-OSC_IN, B5 PA0, C2 PC15, C4 NRST, C6 PB7, D1 PA12, D3 PA14, D5 PA3, E4 PA13, E6 PA2, F3 PA4, G2 PA5, G4 PA6, G6 PA10, H1 PD2, H3 PB5, H5 PA1, J2 PA8, J4 PA7, J6 PA9, K1 LVDS_P, K3 PB15, K5 PC14, L2 LVDS_N, L4 PA15
part B pins: E2 VSS, F1 VDD (power), F5 VHTOL (power), L6 VDDIO (power)

## Socket_WLCSP36_TypeA
designator U?
part A pins: B5 RSTN, C4 PB6, C6 PB3, D3 PB12-OSC32_OUT, D5 PB2, D7 PB0, E4 PB7, E6 PB1, F1 PB14, F3 PB13-OSC32_IN, F5 PB4, F7 PA2-SWDIO, G2 PB15, G6 PA3-SWCLK, H5 PB5, J7 PA1, K6 PA9, L1 OSC_IN, L5 PA10, L7 PA0, M6 PA11, N1 OSC_OUT, N5 RF1, N7 PA8
part B pins: A2 VSSSD, A4 VDDA_VCAP, A6 VDD2, B1 VDDSD, B3 VFBSD, B7 VSSA, D1 VLXSD, J1 VSSSX, J3 VSSIO, K4 VSSIFADC, M2 VDDRF, M4 VSSFTRX

## Socket_WLCSP36_TypeB
designator U?
part A pins: B5 RSTN, C2 PB12-OSC32_OUT, C4 PB6, C6 PB3, D3 PB13-OSC32_IN, D5 PB2, D7 PB0, E2 PB14, E4 PB7, E6 PB1, F3 PB15, F5 PB4, F7 PA1, G4 PB5, G6 PA2-SWDIO, H5 PA3-SWCLK, H7 PA0, J4 PA11, J6 PA9, K1 OSC_IN, K5 PA10, M1 OSC_OUT, M5 RF1, M7 PA8
part B pins: A2 VSSSD, A4 VDDA_VCAP, A6 VDD2, B1 VDDSD, B3 VFBSD, B7 VSSA, D1 VLXSD, H1 VSSSX, K7 VSSIO, L2 VDDRF, L4 VSSFTRX, L6 VSSIFADC

## Socket_WLCSP39_TypeA
designator U?
part A pins: A1 PA14-SWCLK, A3 PA15, A5 PB3-SWO, A7 PB4, B2 PA12, B4 PA13-SWDIO, B6 BOOT0, C1 PA11, C3 PB7, C5 PB8, C7 PC13, C9 PC15-OSC32_OUT, C11 PC14-OSC32_IN, D2 PA8, D4 PA3, D6 PA1, D8 PH1-OSC_OUT, D10 PH0-OSC_IN, E1 PB15, E3 PA5, E5 PA4, E7 PA2, E9 PA0, E11 NRST, F4 PA6, F6 PA7, G5 PB1, G7 PB0
part B pins: A9 VCAP, A11 VDD, B8 VBAT, B10 VSS, F2 VSS, F8 VSS, F10 VSSA, G1 VDD, G3 VCAP, G9 VDD, G11 VDDA

## Socket_WLCSP41_TypeA
designator U?
part A pins: A8 OSC_IN, B7 OSC_OUT, C2 RF, C8 PH3-BOOT0, C10 PB12, D7 PA8, D9 PA6, D11 PA7, E2 NRST, E4 PB15, E6 PA12, E8 PA13-SWDIO, E10 PA1, F1 PA14-SWCLK, F3 PA15, F5 PB4, F7 PC15-OSC32_OUT, F9 PB9, F11 PA2, F13 PA5, G2 PB3-SWO, G8 PC14-OSC32_IN, G10 PB8, G12 PA0
part B pins: A6 VDDRF, A10 VDD, A12 VSSSMPS, B5 VDDANA, B9 VSS, B11 VDD11, B13 VDDSMPS, C4 VDDHPA, C6 VDDRFPA, C12 VLXSMPS, D1 VSSRF, D3 VSSRF, D5 VSSRF, D13 VSSA, E12 VDDA, G4 VDD, G6 VSS

## Socket_WLCSP42_TypeA
designator U?
part A pins: A4 PA15, A6 PB5, A8 PB7, A10 PB8, B3 PA13-SWDIO, B5 PB3, B7 PB6, C2 PA12, C4 PA9, C6 PB4, C8 PF3-BOOT0, C10 PC15-OSC32_OUT, C12 PC14-OSC32_IN, D1 PA11, D3 PA8, D5 PA14-SWCLK, D7 PC13, D9 PF1-OSC_OUT, D11 PF0-OSC_IN, E2 PA10, E4 PA5, E6 PA3, E8 PA1, E12 PF2-NRST, F3 PB1, F5 PB0, F7 PA7, F9 PA0, G4 PB10, G6 PB2, G8 PA6, G10 PA4, G12 PA2
part B pins: A2 VSS, A12 VSS, B1 VDDUSB, B9 VBAT, B11 VDD, E10 VSSA/VREF-, F1 VSS, F11 VDDA/VREF+, G2 VDD

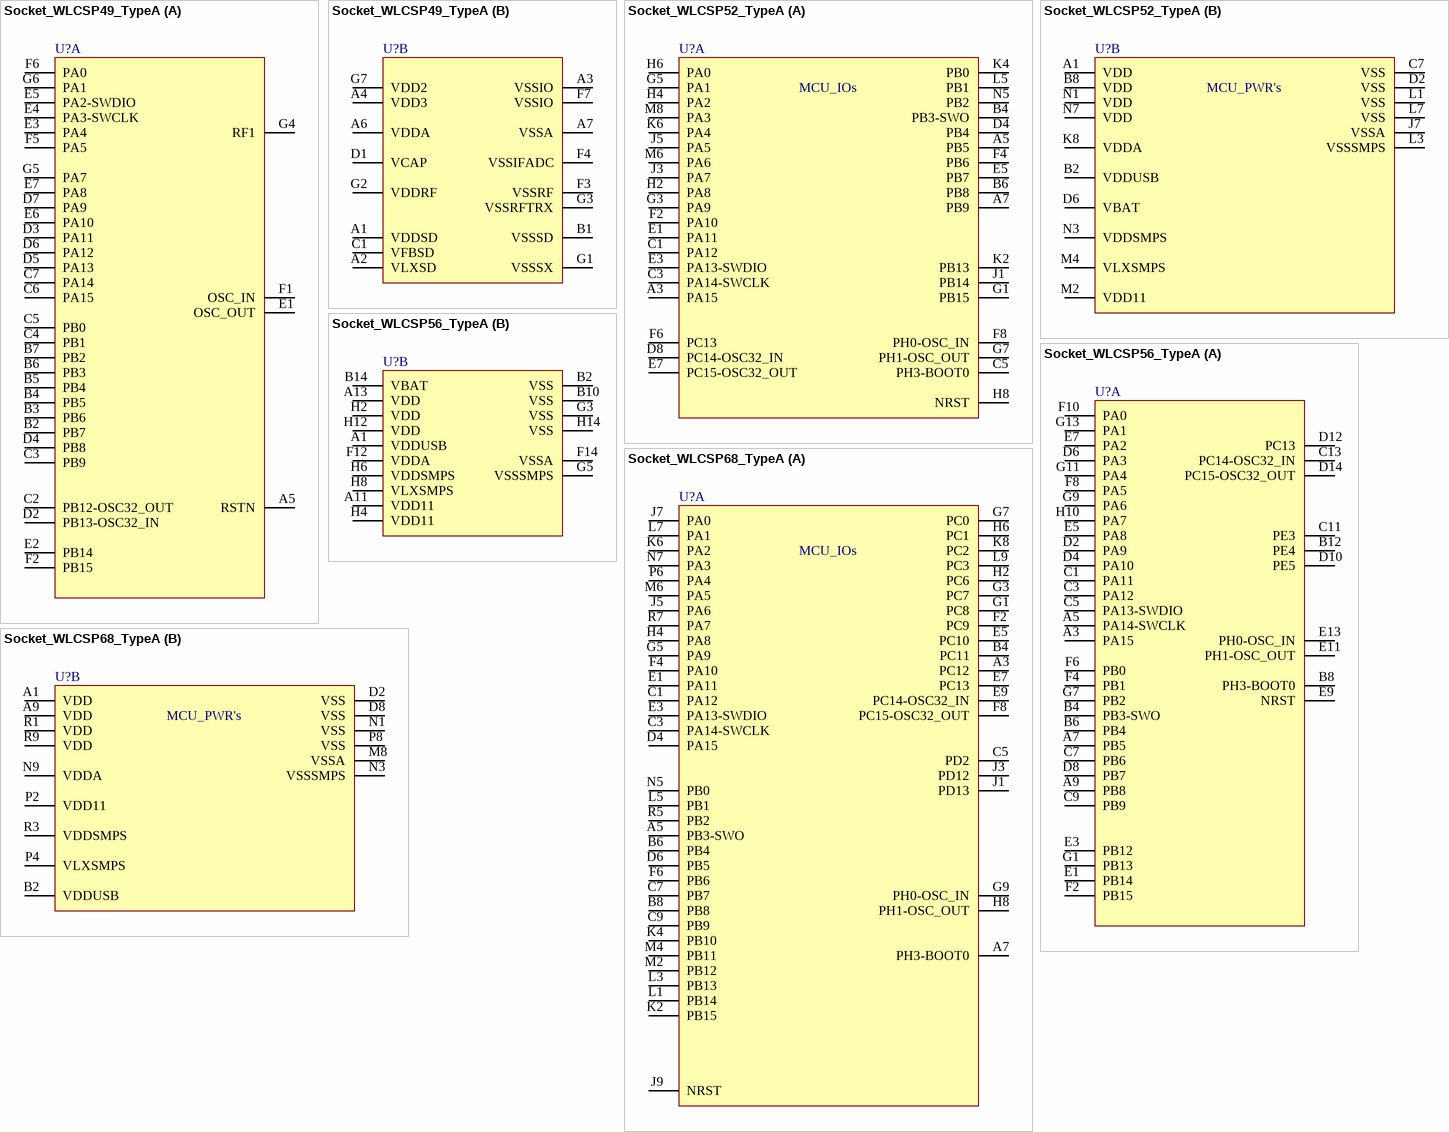
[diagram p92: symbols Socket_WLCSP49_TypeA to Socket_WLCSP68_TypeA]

## Socket_WLCSP49_TypeA
designator U?
part A pins: A5 RSTN, B2 PB7, B3 PB6, B4 PB5, B5 PB4, B6 PB3, B7 PB2, C2 PB12-OSC32_OUT, C3 PB9, C4 PB1, C5 PB0, C6 PA15, C7 PA14, D2 PB13-OSC32_IN, D3 PA11, D4 PB8, D5 PA13, D6 PA12, D7 PA9, E1 OSC_OUT, E2 PB14, E3 PA4, E4 PA3-SWCLK, E5 PA2-SWDIO, E6 PA10, E7 PA8, F1 OSC_IN, F2 PB15, F5 PA5, F6 PA0, G4 RF1, G5 PA7, G6 PA1
part B pins: A1 VDDSD, A2 VLXSD, A3 VSSIO, A4 VDD3, A6 VDDA, A7 VSSA, B1 VSSSD, C1 VFBSD, D1 VCAP, F3 VSSRF, F4 VSSIFADC, F7 VSSIO, G1 VSSSX, G2 VDDRF, G3 VSSRFTRX, G7 VDD2

## Socket_WLCSP52_TypeA
designator U?
part A pins: A3 PA15, A5 PB5, A7 PB9, B4 PB3-SWO, B6 PB8, C1 PA12, C3 PA14-SWCLK, C5 PH3-BOOT0, D4 PB4, D8 PC14-OSC32_IN, E1 PA11, E3 PA13-SWDIO, E5 PB7, E7 PC15-OSC32_OUT, F2 PA10, F4 PB6, F6 PC13, F8 PH0-OSC_IN, G1 PB15, G3 PA9, G5 PA1, G7 PH1-OSC_OUT, H2 PA8, H4 PA2, H6 PA0, H8 NRST, J1 PB14, J3 PA7, J5 PA5, K2 PB13, K4 PB0, K6 PA4, L5 PB1, M6 PA6, M8 PA3, N5 PB2
part B pins: A1 VDD, B2 VDDUSB, B8 VDD, C7 VSS, D2 VSS, D6 VBAT, J7 VSSA, K8 VDDA, L1 VSS, L3 VSSSMPS, L7 VSS, M2 VDD11, M4 VLXSMPS, N1 VDD, N3 VDDSMPS, N7 VDD

## Socket_WLCSP56_TypeA
designator U?
part A pins: A3 PA15, A5 PA14-SWCLK, A7 PB5, A9 PB8, B4 PB3-SWO, B6 PB4, B8 PH3-BOOT0, B12 PE4, C1 PA11, C3 PA12, C5 PA13-SWDIO, C7 PB6, C9 PB9, C11 PE3, C13 PC14-OSC32_IN, D2 PA9, D4 PA10, D6 PA3, D8 PB7, D10 PE5, D12 PC13, D14 PC15-OSC32_OUT, E1 PB14, E3 PB12, E5 PA8, E7 PA2, E9 NRST, E11 PH1-OSC_OUT, E13 PH0-OSC_IN, F2 PB15, F4 PB1, F6 PB0, F8 PA5, F10 PA0, G1 PB13, G7 PB2, G9 PA6, G11 PA4, G13 PA1, H10 PA7
part B pins: A1 VDDUSB, A11 VDD11, A13 VDD, B2 VSS, B10 VSS, B14 VBAT, F12 VDDA, F14 VSSA, G3 VSS, G5 VSSSMPS, H2 VDD, H4 VDD11, H6 VDDSMPS, H8 VLXSMPS, H12 VDD, H14 VSS

## Socket_WLCSP68_TypeA
designator U?
part A pins: A3 PC12, A5 PB3-SWO, A7 PH3-BOOT0, B4 PC11, B6 PB4, B8 PB8, C1 PA12, C3 PA14-SWCLK, C5 PD2, C7 PB7, C9 PB9, D4 PA15, D6 PB5, E1 PA11, E3 PA13-SWDIO, E5 PC10, E7 PC13, E9 PC14-OSC32_IN, F2 PC9, F4 PA10, F6 PB6, F8 PC15-OSC32_OUT, G1 PC8, G3 PC7, G5 PA9, G7 PC0, G9 PH0-OSC_IN, H2 PC6, H4 PA8, H6 PC1, H8 PH1-OSC_OUT, J1 PD13, J3 PD12, J5 PA6, J7 PA0, J9 NRST, K2 PB15, K4 PB10, K6 PA2, K8 PC2, L1 PB14, L3 PB13, L5 PB1, L7 PA1, L9 PC3, M2 PB12, M4 PB11, M6 PA5, N5 PB0, N7 PA3, P6 PA4, R5 PB2, R7 PA7
part B pins: A1 VDD, A9 VDD, B2 VDDUSB, D2 VSS, D8 VSS, M8 VSSA, N1 VSS, N3 VSSSMPS, N9 VDDA, P2 VDD11, P4 VLXSMPS, P8 VSS, R1 VDD, R3 VDDSMPS, R9 VDD

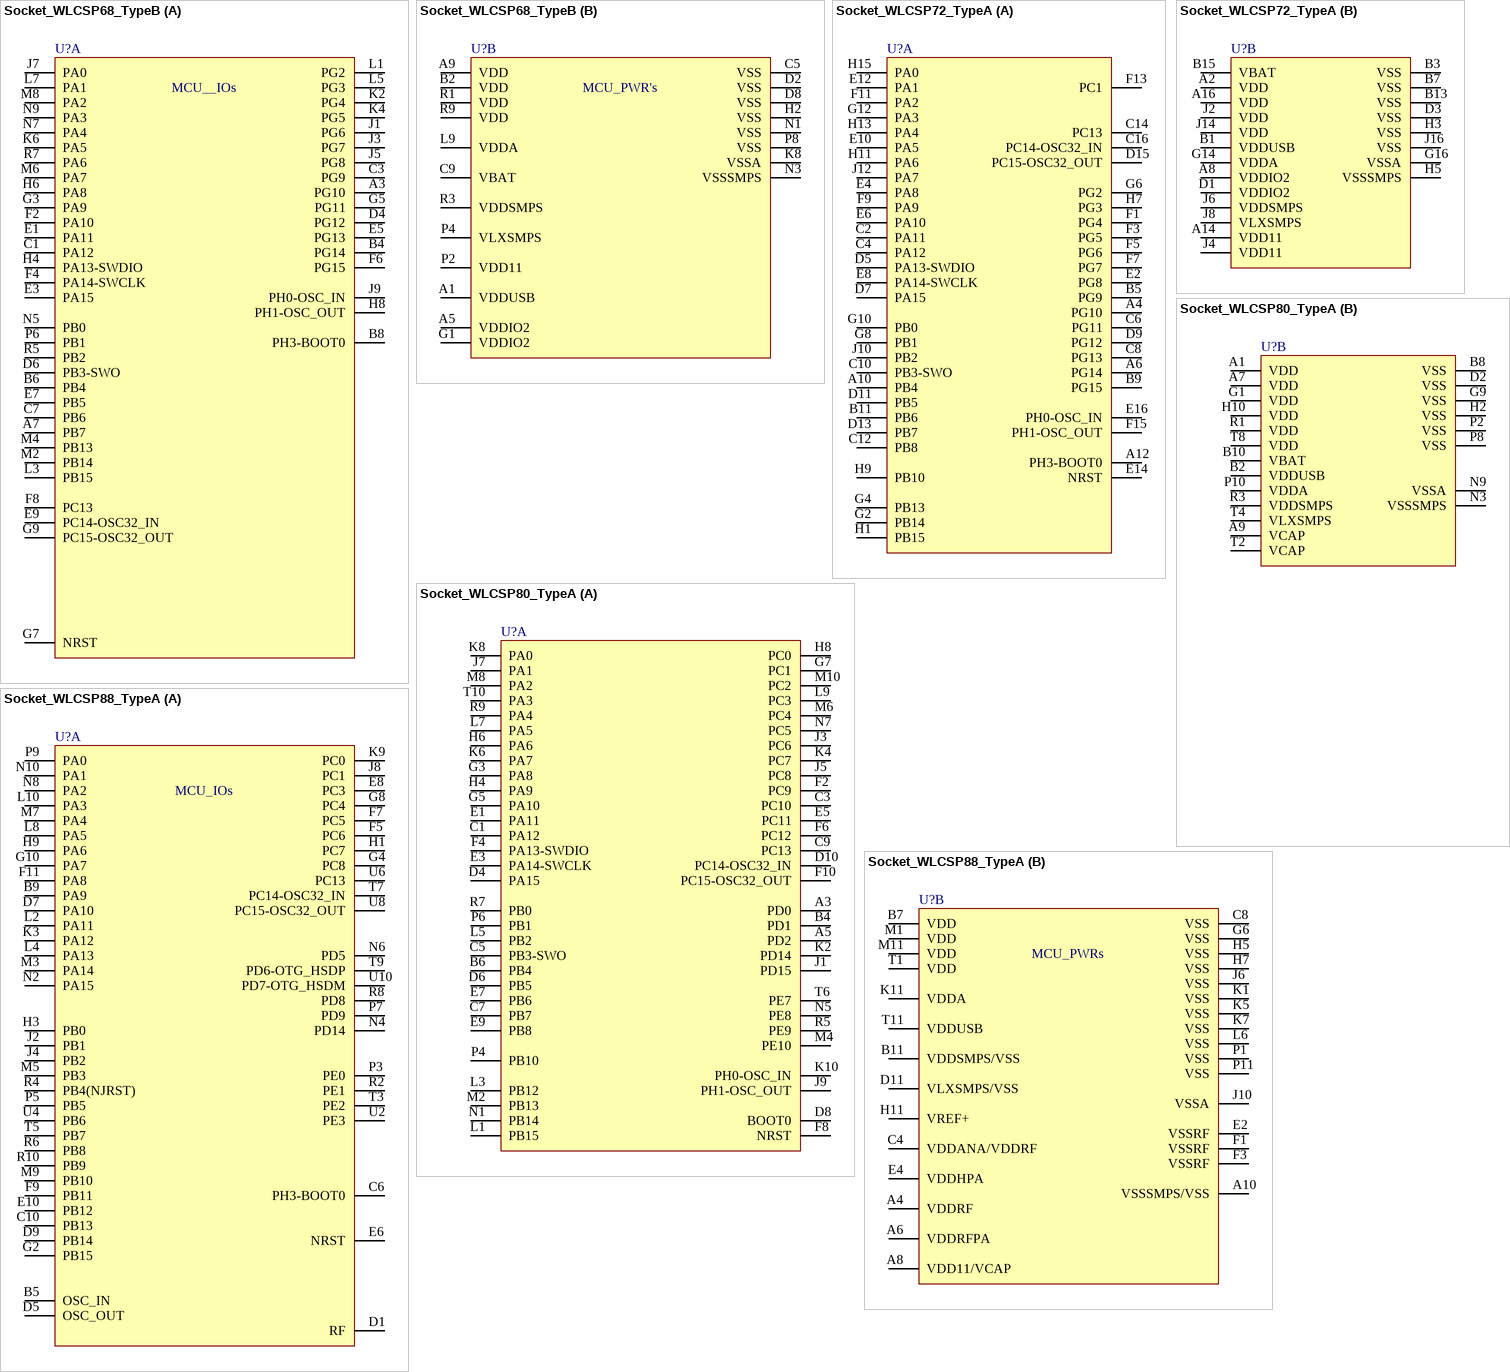
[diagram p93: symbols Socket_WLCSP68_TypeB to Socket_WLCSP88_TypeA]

## Socket_WLCSP68_TypeB
designator U?
part A pins: A3 PG10, A7 PB7, B4 PG14, B6 PB4, B8 PH3-BOOT0, C1 PA12, C3 PG9, C7 PB6, D4 PG12, D6 PB3-SWO, E1 PA11, E3 PA15, E5 PG13, E7 PB5, E9 PC14-OSC32_IN, F2 PA10, F4 PA14-SWCLK, F6 PG15, F8 PC13, G3 PA9, G5 PG11, G7 NRST, G9 PC15-OSC32_OUT, H4 PA13-SWDIO, H6 PA8, H8 PH1-OSC_OUT, J1 PG6, J3 PG7, J5 PG8, J7 PA0, J9 PH0-OSC_IN, K2 PG4, K4 PG5, K6 PA5, L1 PG2, L3 PB15, L5 PG3, L7 PA1, M2 PB14, M4 PB13, M6 PA7, M8 PA2, N5 PB0, N7 PA4, N9 PA3, P6 PB1, R5 PB2, R7 PA6
part B pins: A1 VDDUSB, A5 VDDIO2, A9 VDD, B2 VDD, C5 VSS, C9 VBAT, D2 VSS, D8 VSS, G1 VDDIO2, H2 VSS, K8 VSSA, L9 VDDA, N1 VSS, N3 VSSSMPS, P2 VDD11, P4 VLXSMPS, P8 VSS, R1 VDD, R3 VDDSMPS, R9 VDD

## Socket_WLCSP72_TypeA
designator U?
part A pins: A4 PG10, A6 PG14, A10 PB4, A12 PH3-BOOT0, B5 PG9, B9 PG15, B11 PB6, C2 PA11, C4 PA12, C6 PG11, C8 PG13, C10 PB3-SWO, C12 PB8, C14 PC13, C16 PC14-OSC32_IN, D5 PA13-SWDIO, D7 PA15, D9 PG12, D11 PB5, D13 PB7, D15 PC15-OSC32_OUT, E2 PG8, E4 PA8, E6 PA10, E8 PA14-SWCLK, E10 PA5, E12 PA1, E14 NRST, E16 PH0-OSC_IN, F1 PG4, F3 PG5, F5 PG6, F7 PG7, F9 PA9, F11 PA2, F13 PC1, F15 PH1-OSC_OUT, G2 PB14, G4 PB13, G6 PG2, G8 PB1, G10 PB0, G12 PA3, H1 PB15, H7 PG3, H9 PB10, H11 PA6, H13 PA4, H15 PA0, J10 PB2, J12 PA7
part B pins: A2 VDD, A8 VDDIO2, A14 VDD11, A16 VDD, B1 VDDUSB, B3 VSS, B7 VSS, B13 VSS, B15 VBAT, D1 VDDIO2, D3 VSS, G14 VDDA, G16 VSSA, H3 VSS, H5 VSSSMPS, J2 VDD, J4 VDD11, J6 VDDSMPS, J8 VLXSMPS, J14 VDD, J16 VSS

## Socket_WLCSP80_TypeA
designator U?
part A pins: A3 PD0, A5 PD2, B4 PD1, B6 PB4, C1 PA12, C3 PC10, C5 PB3-SWO, C7 PB7, C9 PC13, D4 PA15, D6 PB5, D8 BOOT0, D10 PC14-OSC32_IN, E1 PA11, E3 PA14-SWCLK, E5 PC11, E7 PB6, E9 PB8, F2 PC9, F4 PA13-SWDIO, F6 PC12, F8 NRST, F10 PC15-OSC32_OUT, G3 PA8, G5 PA10, G7 PC1, H4 PA9, H6 PA6, H8 PC0, J1 PD15, J3 PC6, J5 PC8, J7 PA1, J9 PH1-OSC_OUT, K2 PD14, K4 PC7, K6 PA7, K8 PA0, K10 PH0-OSC_IN, L1 PB15, L3 PB12, L5 PB2, L7 PA5, L9 PC3, M2 PB13, M4 PE10, M6 PC4, M8 PA2, M10 PC2, N1 PB14, N5 PE8, N7 PC5, P4 PB10, P6 PB1, R5 PE9, R7 PB0, R9 PA4, T6 PE7, T10 PA3
part B pins: A1 VDD, A7 VDD, A9 VCAP, B2 VDDUSB, B8 VSS, B10 VBAT, D2 VSS, G1 VDD, G9 VSS, H2 VSS, H10 VDD, N3 VSSSMPS, N9 VSSA, P2 VSS, P8 VSS, P10 VDDA, R1 VDD, R3 VDDSMPS, T2 VCAP, T4 VLXSMPS, T8 VDD

## Socket_WLCSP88_TypeA
designator U?
part A pins: B5 OSC_IN, B9 PA9, C6 PH3-BOOT0, C10 PB13, D1 RF, D5 OSC_OUT, D7 PA10, D9 PB14, E6 NRST, E8 PC3, E10 PB12, F5 PC6, F7 PC5, F9 PB11, F11 PA8, G2 PB15, G4 PC8, G8 PC4, G10 PA7, H1 PC7, H3 PB0, H9 PA6, J2 PB1, J4 PB2, J8 PC1, K3 PA12, K9 PC0, L2 PA11, L4 PA13, L8 PA5, L10 PA3, M3 PA14, M5 PB3, M7 PA4, M9 PB10, N2 PA15, N4 PD14, N6 PD5, N8 PA2, N10 PA1, P3 PE0, P5 PB5, P7 PD9, P9 PA0, R2 PE1, R4 PB4(NJRST), R6 PB8, R8 PD8, R10 PB9, T3 PE2, T5 PB7, T7 PC14-OSC32_IN, T9 PD6-OTG_HSDP, U2 PE3, U4 PB6, U6 PC13, U8 PC15-OSC32_OUT, U10 PD7-OTG_HSDM
part B pins: A4 VDDRF, A6 VDDRFPA, A8 VDD11/VCAP, A10 VSSSMPS/VSS, B7 VDD, B11 VDDSMPS/VSS, C4 VDDANA/VDDRF, C8 VSS, D11 VLXSMPS/VSS, E2 VSSRF, E4 VDDHPA, F1 VSSRF, F3 VSSRF, G6 VSS, H5 VSS, H7 VSS, H11 VREF+, J6 VSS, J10 VSSA, K1 VSS, K5 VSS, K7 VSS, K11 VDDA, L6 VSS, M1 VDD, M11 VDD, P1 VSS, P11 VSS, T1 VDD, T11 VDDUSB

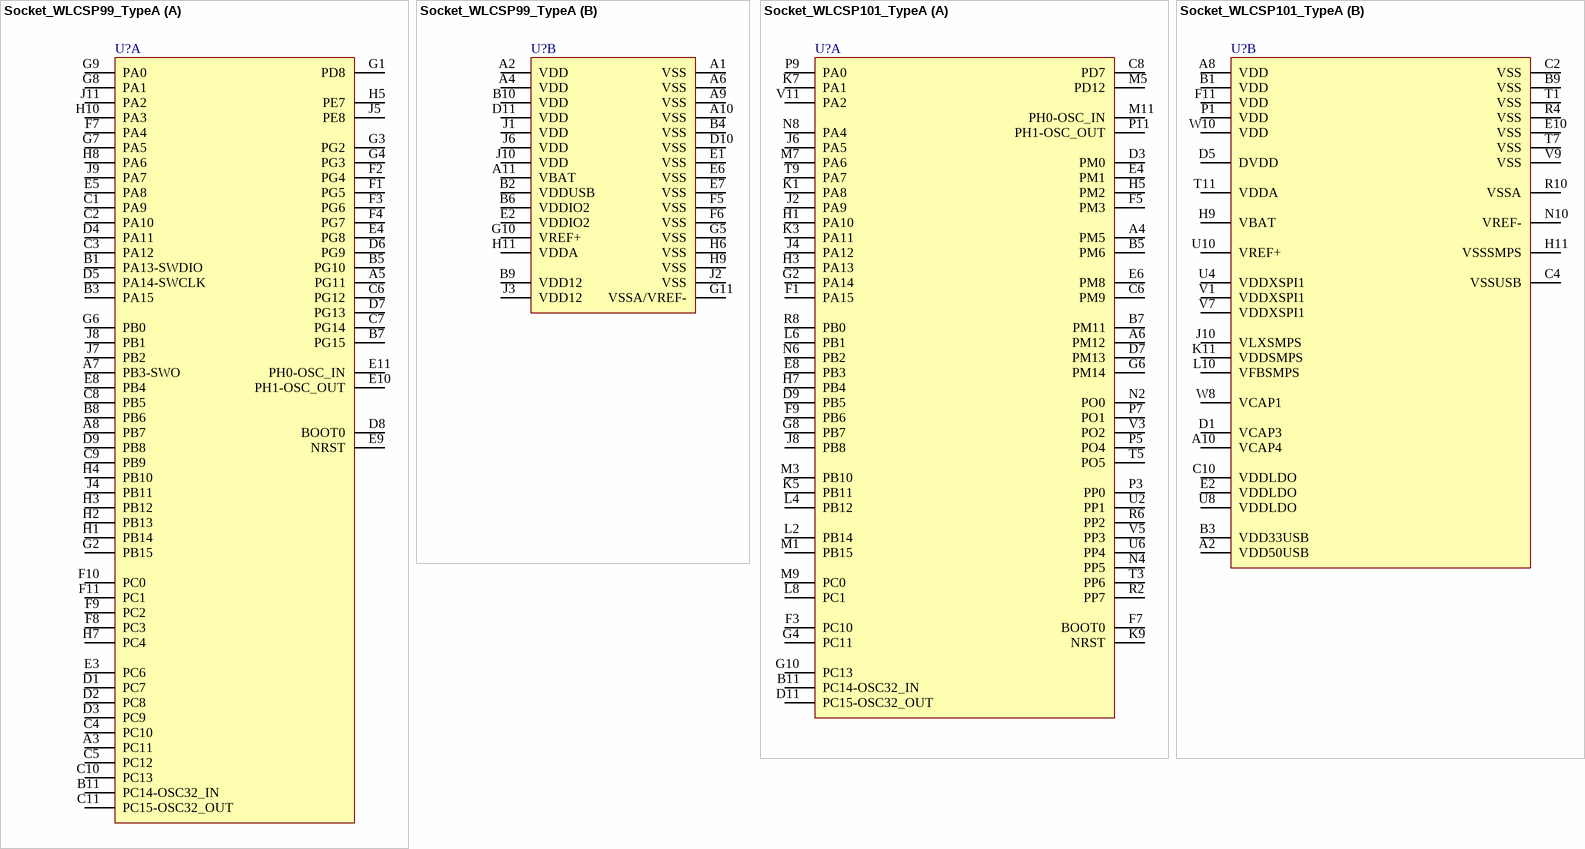
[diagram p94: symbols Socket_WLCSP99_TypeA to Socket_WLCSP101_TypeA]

## Socket_WLCSP99_TypeA
designator U?
part A pins: A3 PC11, A5 PG11, A7 PB3-SWO, A8 PB7, B1 PA13-SWDIO, B3 PA15, B5 PG10, B7 PG15, B8 PB6, B11 PC14-OSC32_IN, C1 PA9, C2 PA10, C3 PA12, C4 PC10, C5 PC12, C6 PG12, C7 PG14, C8 PB5, C9 PB9, C10 PC13, C11 PC15-OSC32_OUT, D1 PC7, D2 PC8, D3 PC9, D4 PA11, D5 PA14-SWCLK, D6 PG9, D7 PG13, D8 BOOT0, D9 PB8, E3 PC6, E4 PG8, E5 PA8, E8 PB4, E9 NRST, E10 PH1-OSC_OUT, E11 PH0-OSC_IN, F1 PG5, F2 PG4, F3 PG6, F4 PG7, F7 PA4, F8 PC3, F9 PC2, F10 PC0, F11 PC1, G1 PD8, G2 PB15, G3 PG2, G4 PG3, G6 PB0, G7 PA5, G8 PA1, G9 PA0, H1 PB14, H2 PB13, H3 PB12, H4 PB10, H5 PE7, H7 PC4, H8 PA6, H10 PA3, J4 PB11, J5 PE8, J7 PB2, J8 PB1, J9 PA7, J11 PA2
part B pins: A1 VSS, A2 VDD, A4 VDD, A6 VSS, A9 VSS, A10 VSS, A11 VBAT, B2 VDDUSB, B4 VSS, B6 VDDIO2, B9 VDD12, B10 VDD, D10 VSS, D11 VDD, E1 VSS, E2 VDDIO2, E6 VSS, E7 VSS, F5 VSS, F6 VSS, G5 VSS, G10 VREF+, G11 VSSA/VREF-, H6 VSS, H9 VSS, H11 VDDA, J1 VDD, J2 VSS, J3 VDD12, J6 VDD, J10 VDD

## Socket_WLCSP101_TypeA
designator U?
part A pins: A4 PM5, A6 PM12, B5 PM6, B7 PM11, B11 PC14-OSC32_IN, C6 PM9, C8 PD7, D3 PM0, D7 PM13, D9 PB5, D11 PC15-OSC32_OUT, E4 PM1, E6 PM8, E8 PB3, F1 PA15, F3 PC10, F5 PM3, F7 BOOT0, F9 PB6, G2 PA14, G4 PC11, G6 PM14, G8 PB7, G10 PC13, H1 PA10, H3 PA13, H5 PM2, H7 PB4, J2 PA9, J4 PA12, J6 PA5, J8 PB8, K1 PA8, K3 PA11, K5 PB11, K7 PA1, K9 NRST, L2 PB14, L4 PB12, L6 PB1, L8 PC1, M1 PB15, M3 PB10, M5 PD12, M7 PA6, M9 PC0, M11 PH0-OSC_IN, N2 PO0, N4 PP5, N6 PB2, N8 PA4, P3 PP0, P5 PO4, P7 PO1, P9 PA0, P11 PH1-OSC_OUT, R2 PP7, R6 PP2, R8 PB0, T3 PP6, T5 PO5, T9 PA7, U2 PP1, U6 PP4, V3 PO2, V5 PP3, V11 PA2
part B pins: A2 VDD50USB, A8 VDD, A10 VCAP4, B1 VDD, B3 VDD33USB, B9 VSS, C2 VSS, C4 VSSUSB, C10 VDDLDO, D1 VCAP3, D5 DVDD, E2 VDDLDO, E10 VSS, F11 VDD, H9 VBAT, H11 VSSSMPS, J10 VLXSMPS, K11 VDDSMPS, L10 VFBSMPS, N10 VREF-, P1 VDD, R4 VSS, R10 VSSA, T1 VSS, T7 VSS, T11 VDDA, U4 VDDXSPI1, U8 VDDLDO, U10 VREF+, V1 VDDXSPI1, V7 VDDXSPI1, V9 VSS, W8 VCAP1, W10 VDD

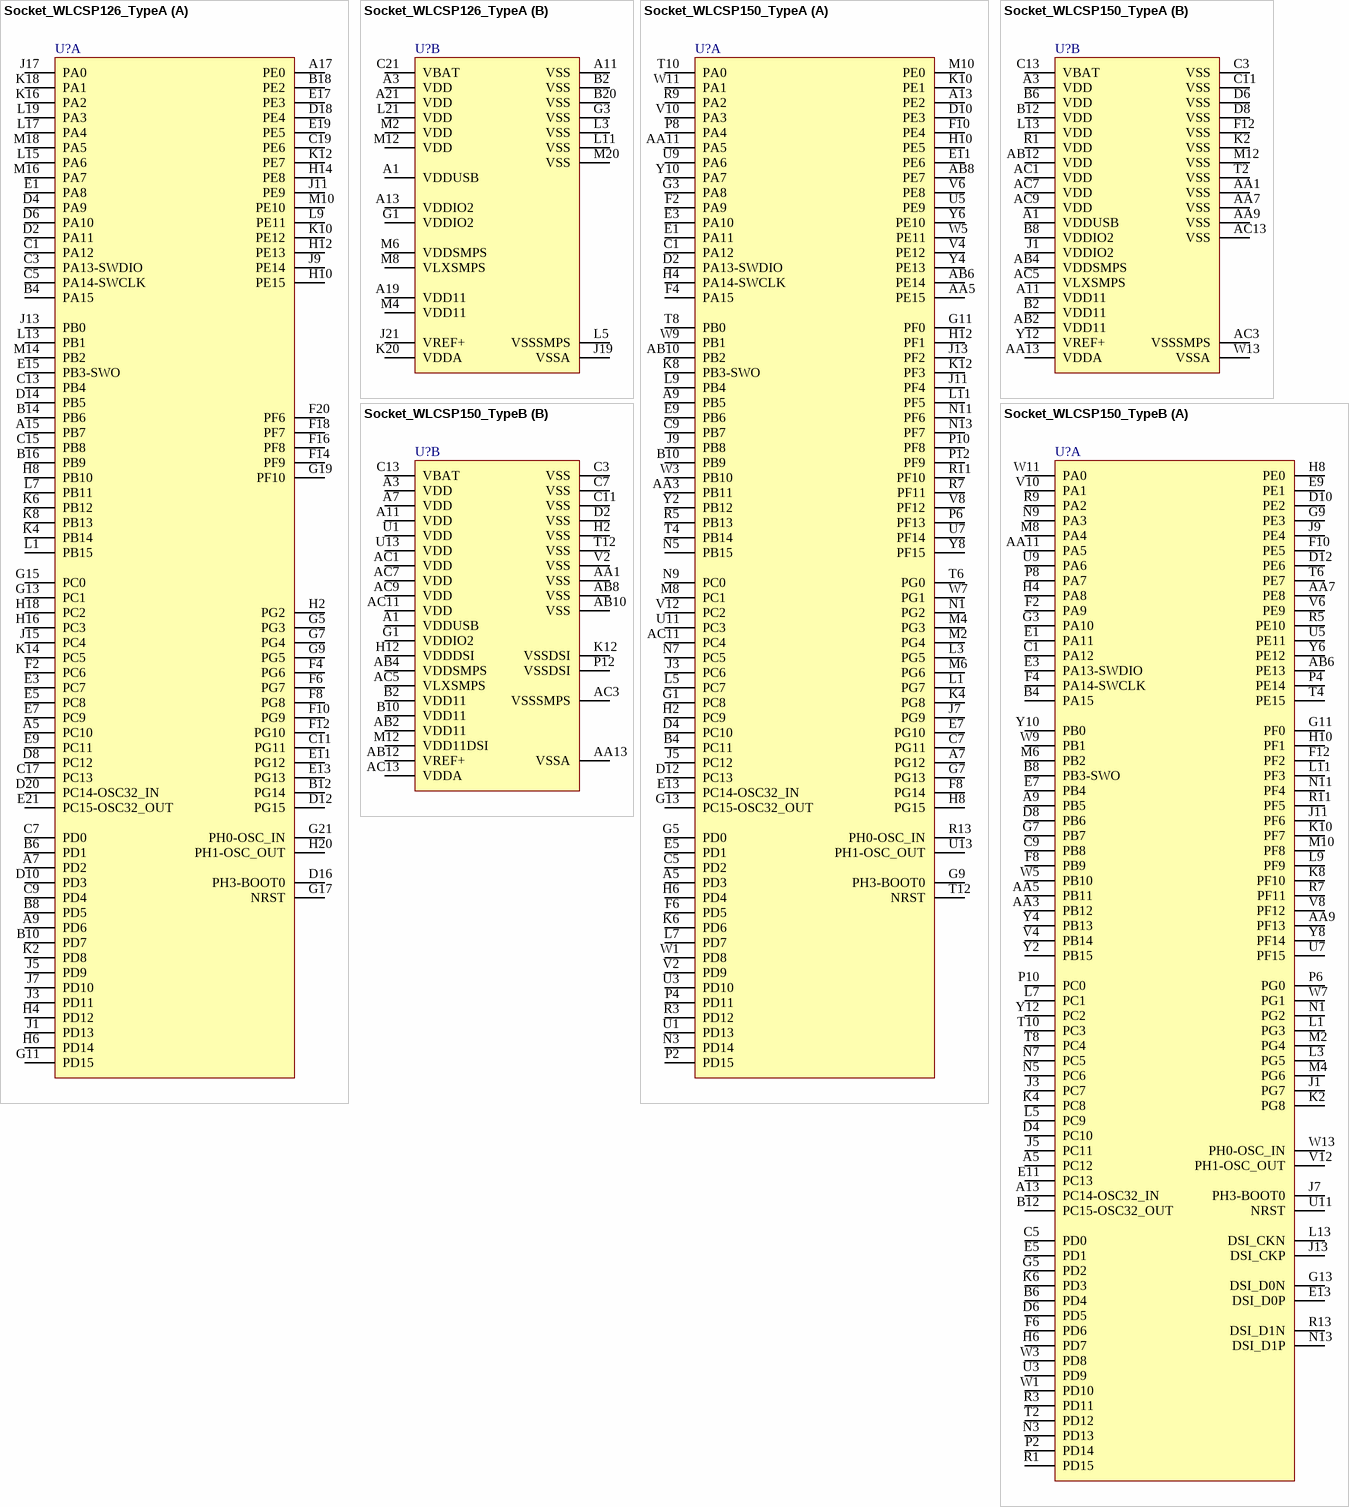
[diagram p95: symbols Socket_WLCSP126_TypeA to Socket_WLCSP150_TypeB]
